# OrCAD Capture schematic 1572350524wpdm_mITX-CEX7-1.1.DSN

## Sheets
1 CEX7-Interface: size D; title: COM express type 7 interface; rev: 1.1
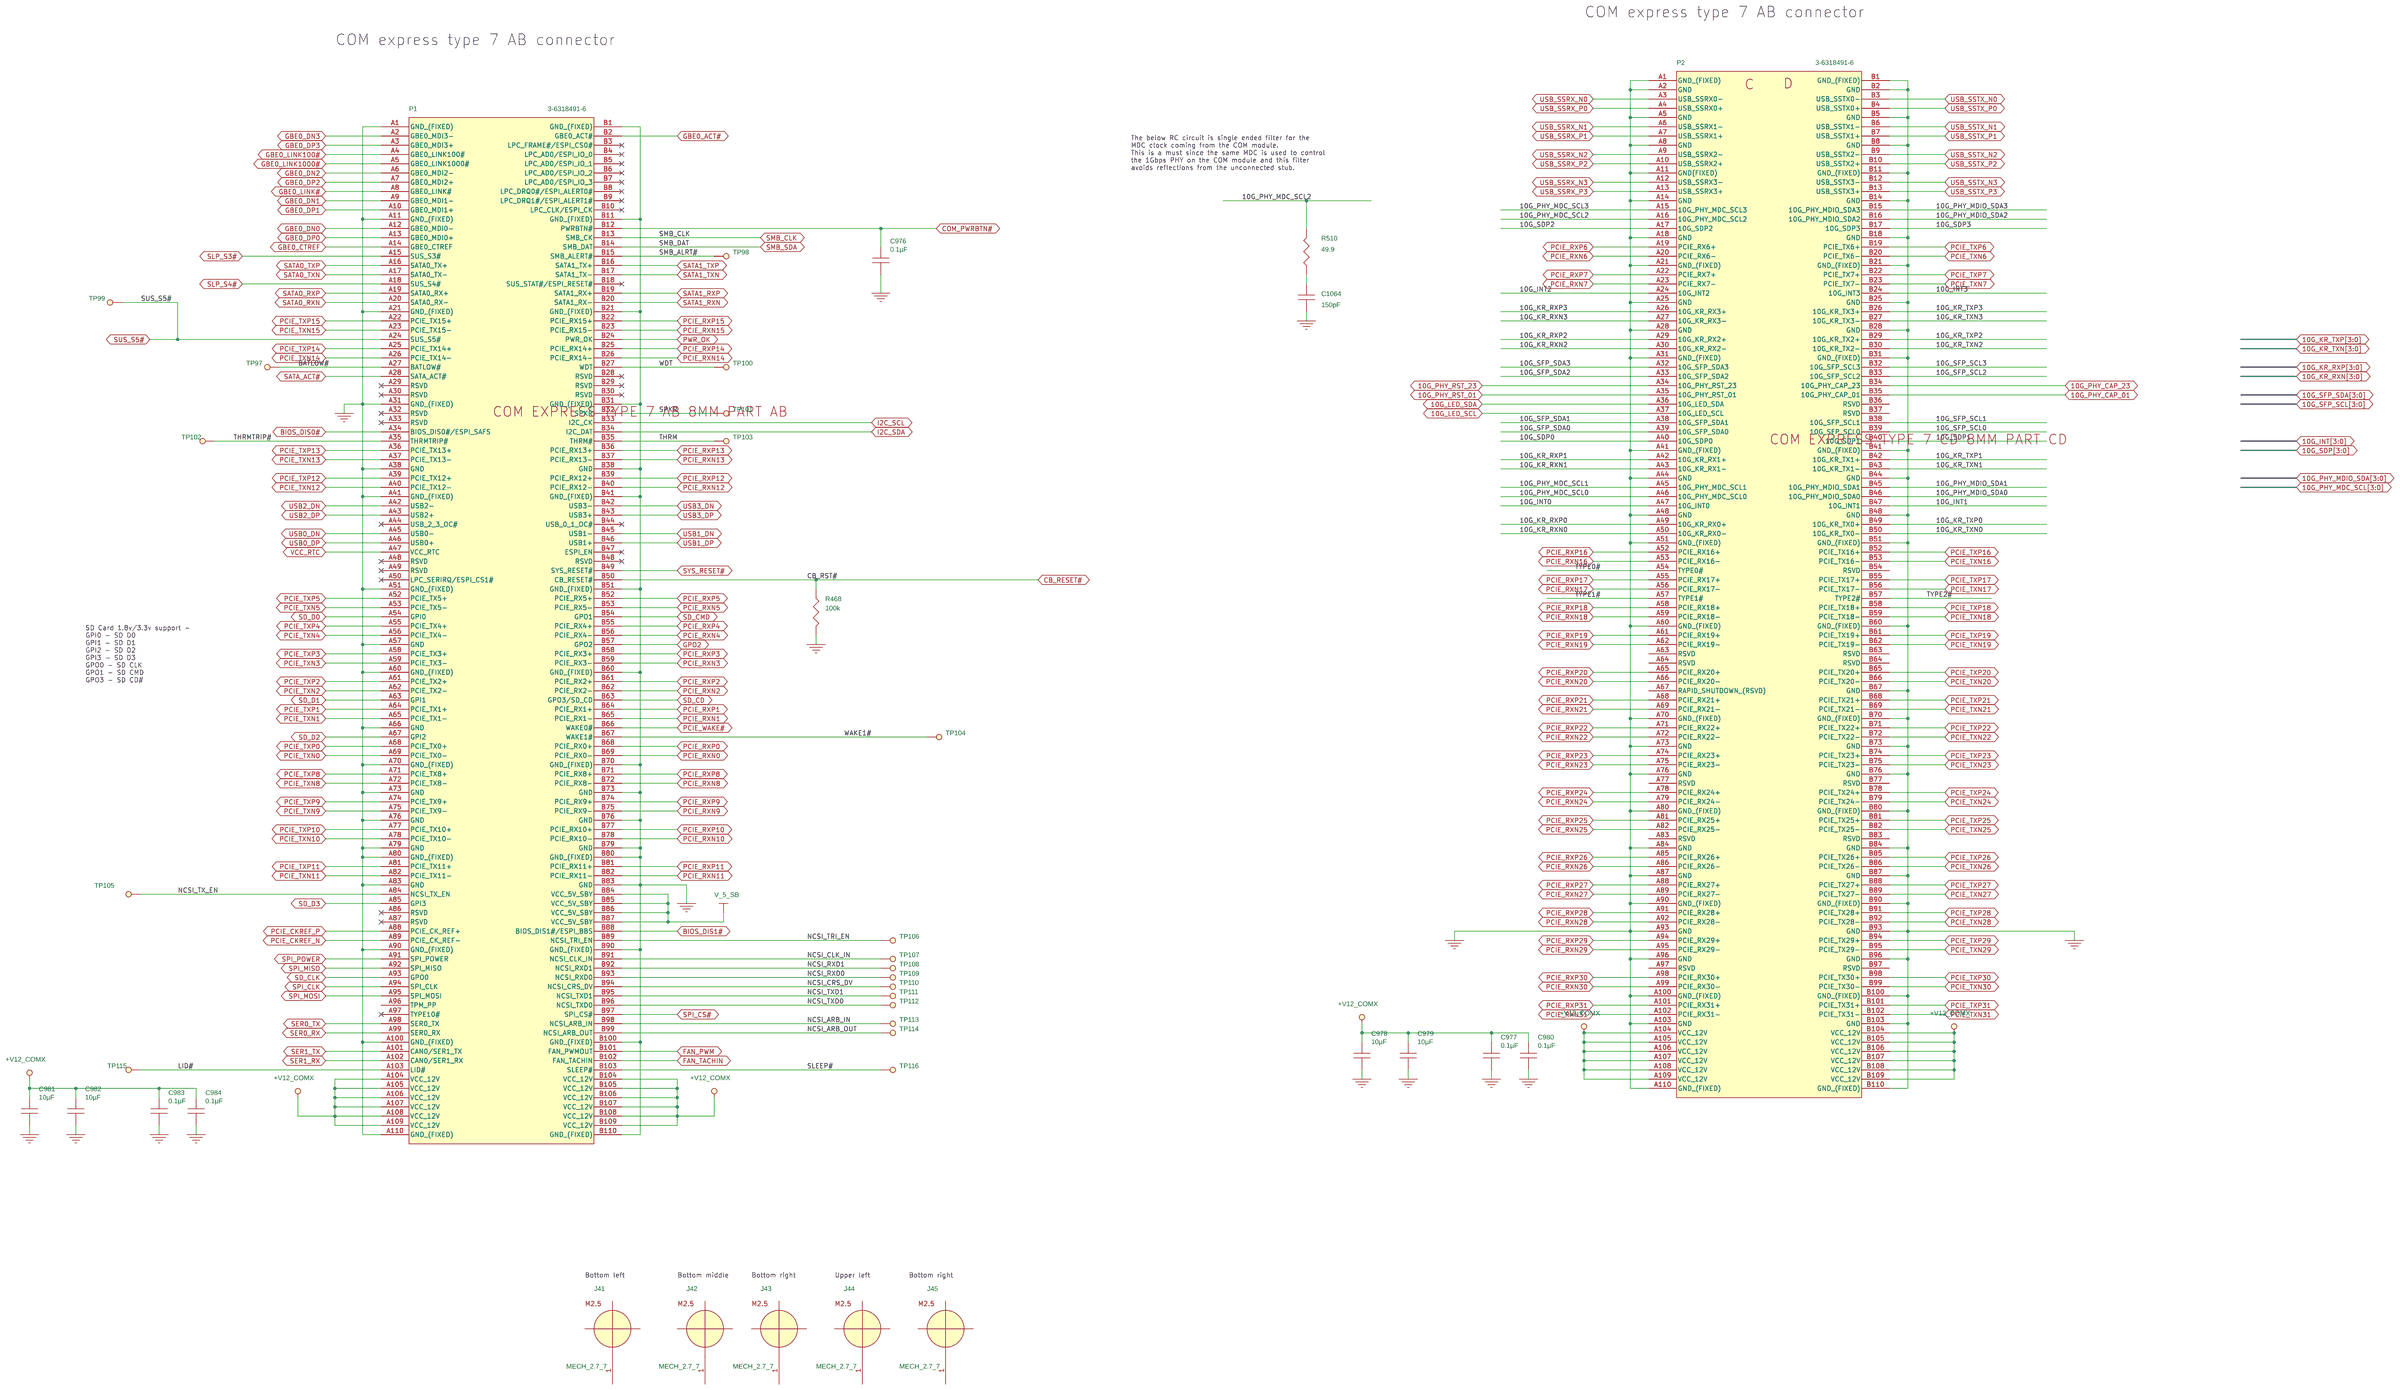
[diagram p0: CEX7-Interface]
2 Connectors: size D; title: PCIe, SATA, NVME, FANs, micro SD, RJ45 and QSFP28 connectors
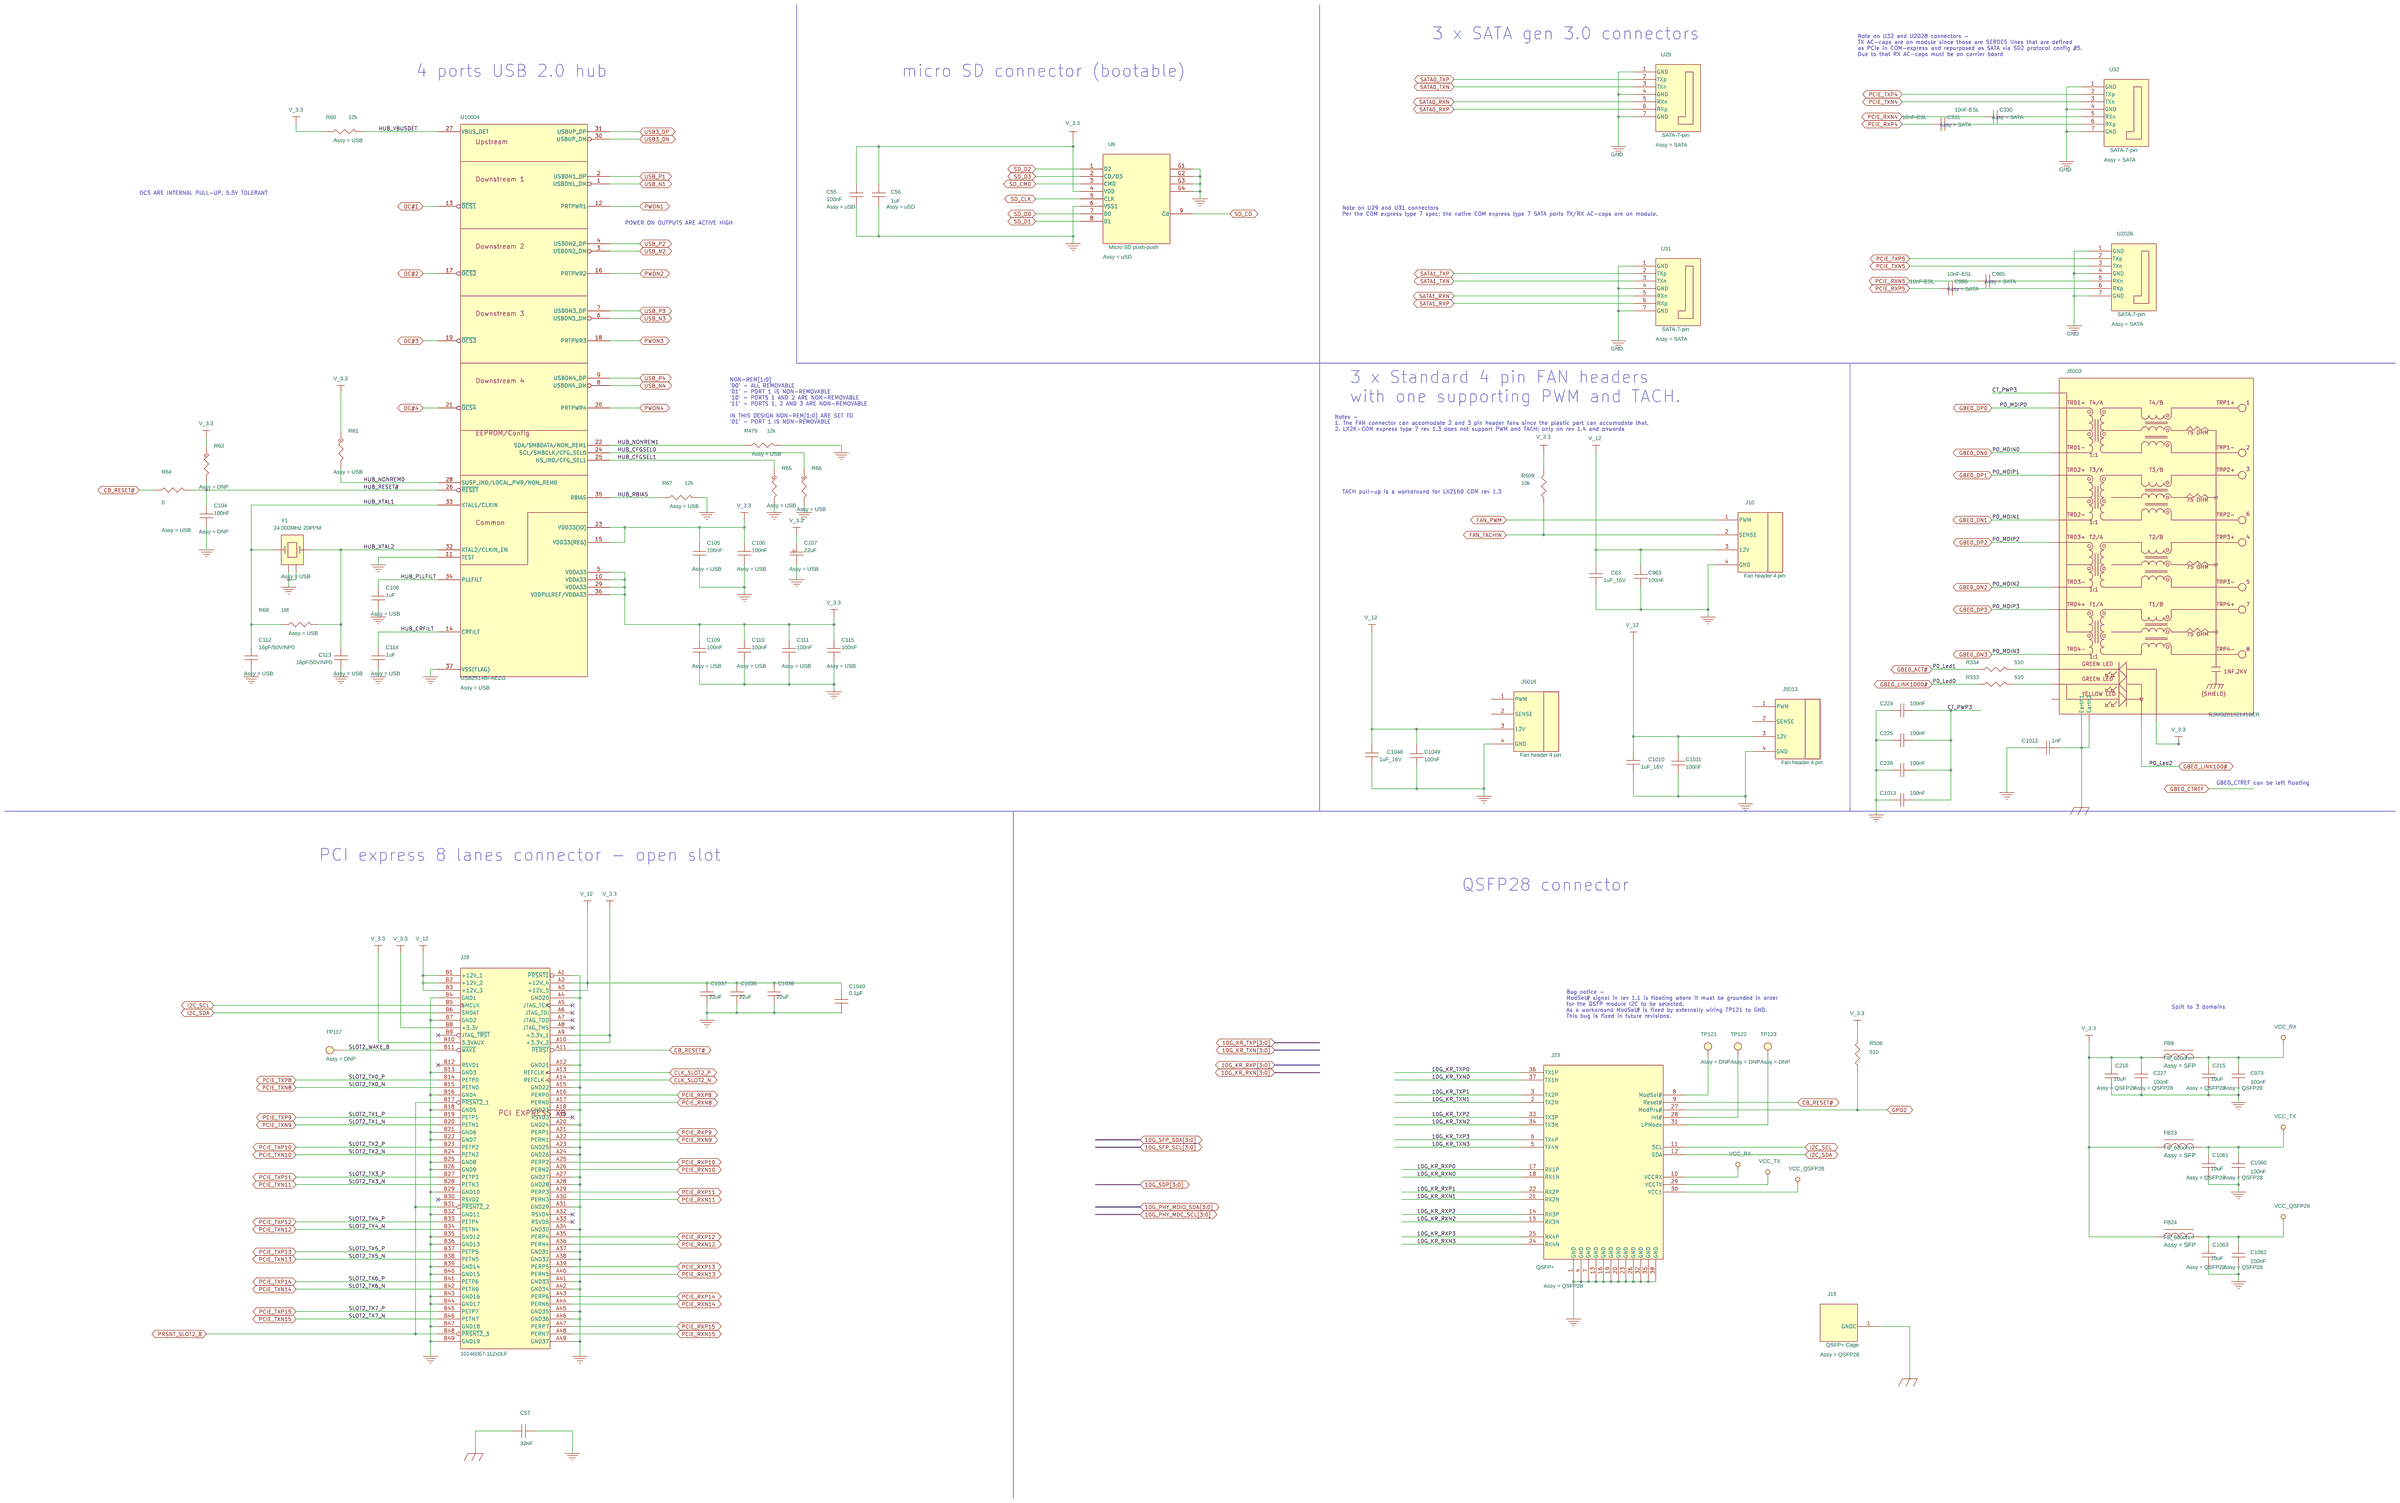
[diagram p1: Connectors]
3 Connectors (2): size D; title: Micro BMC, NVME, USB serial, USB connectors
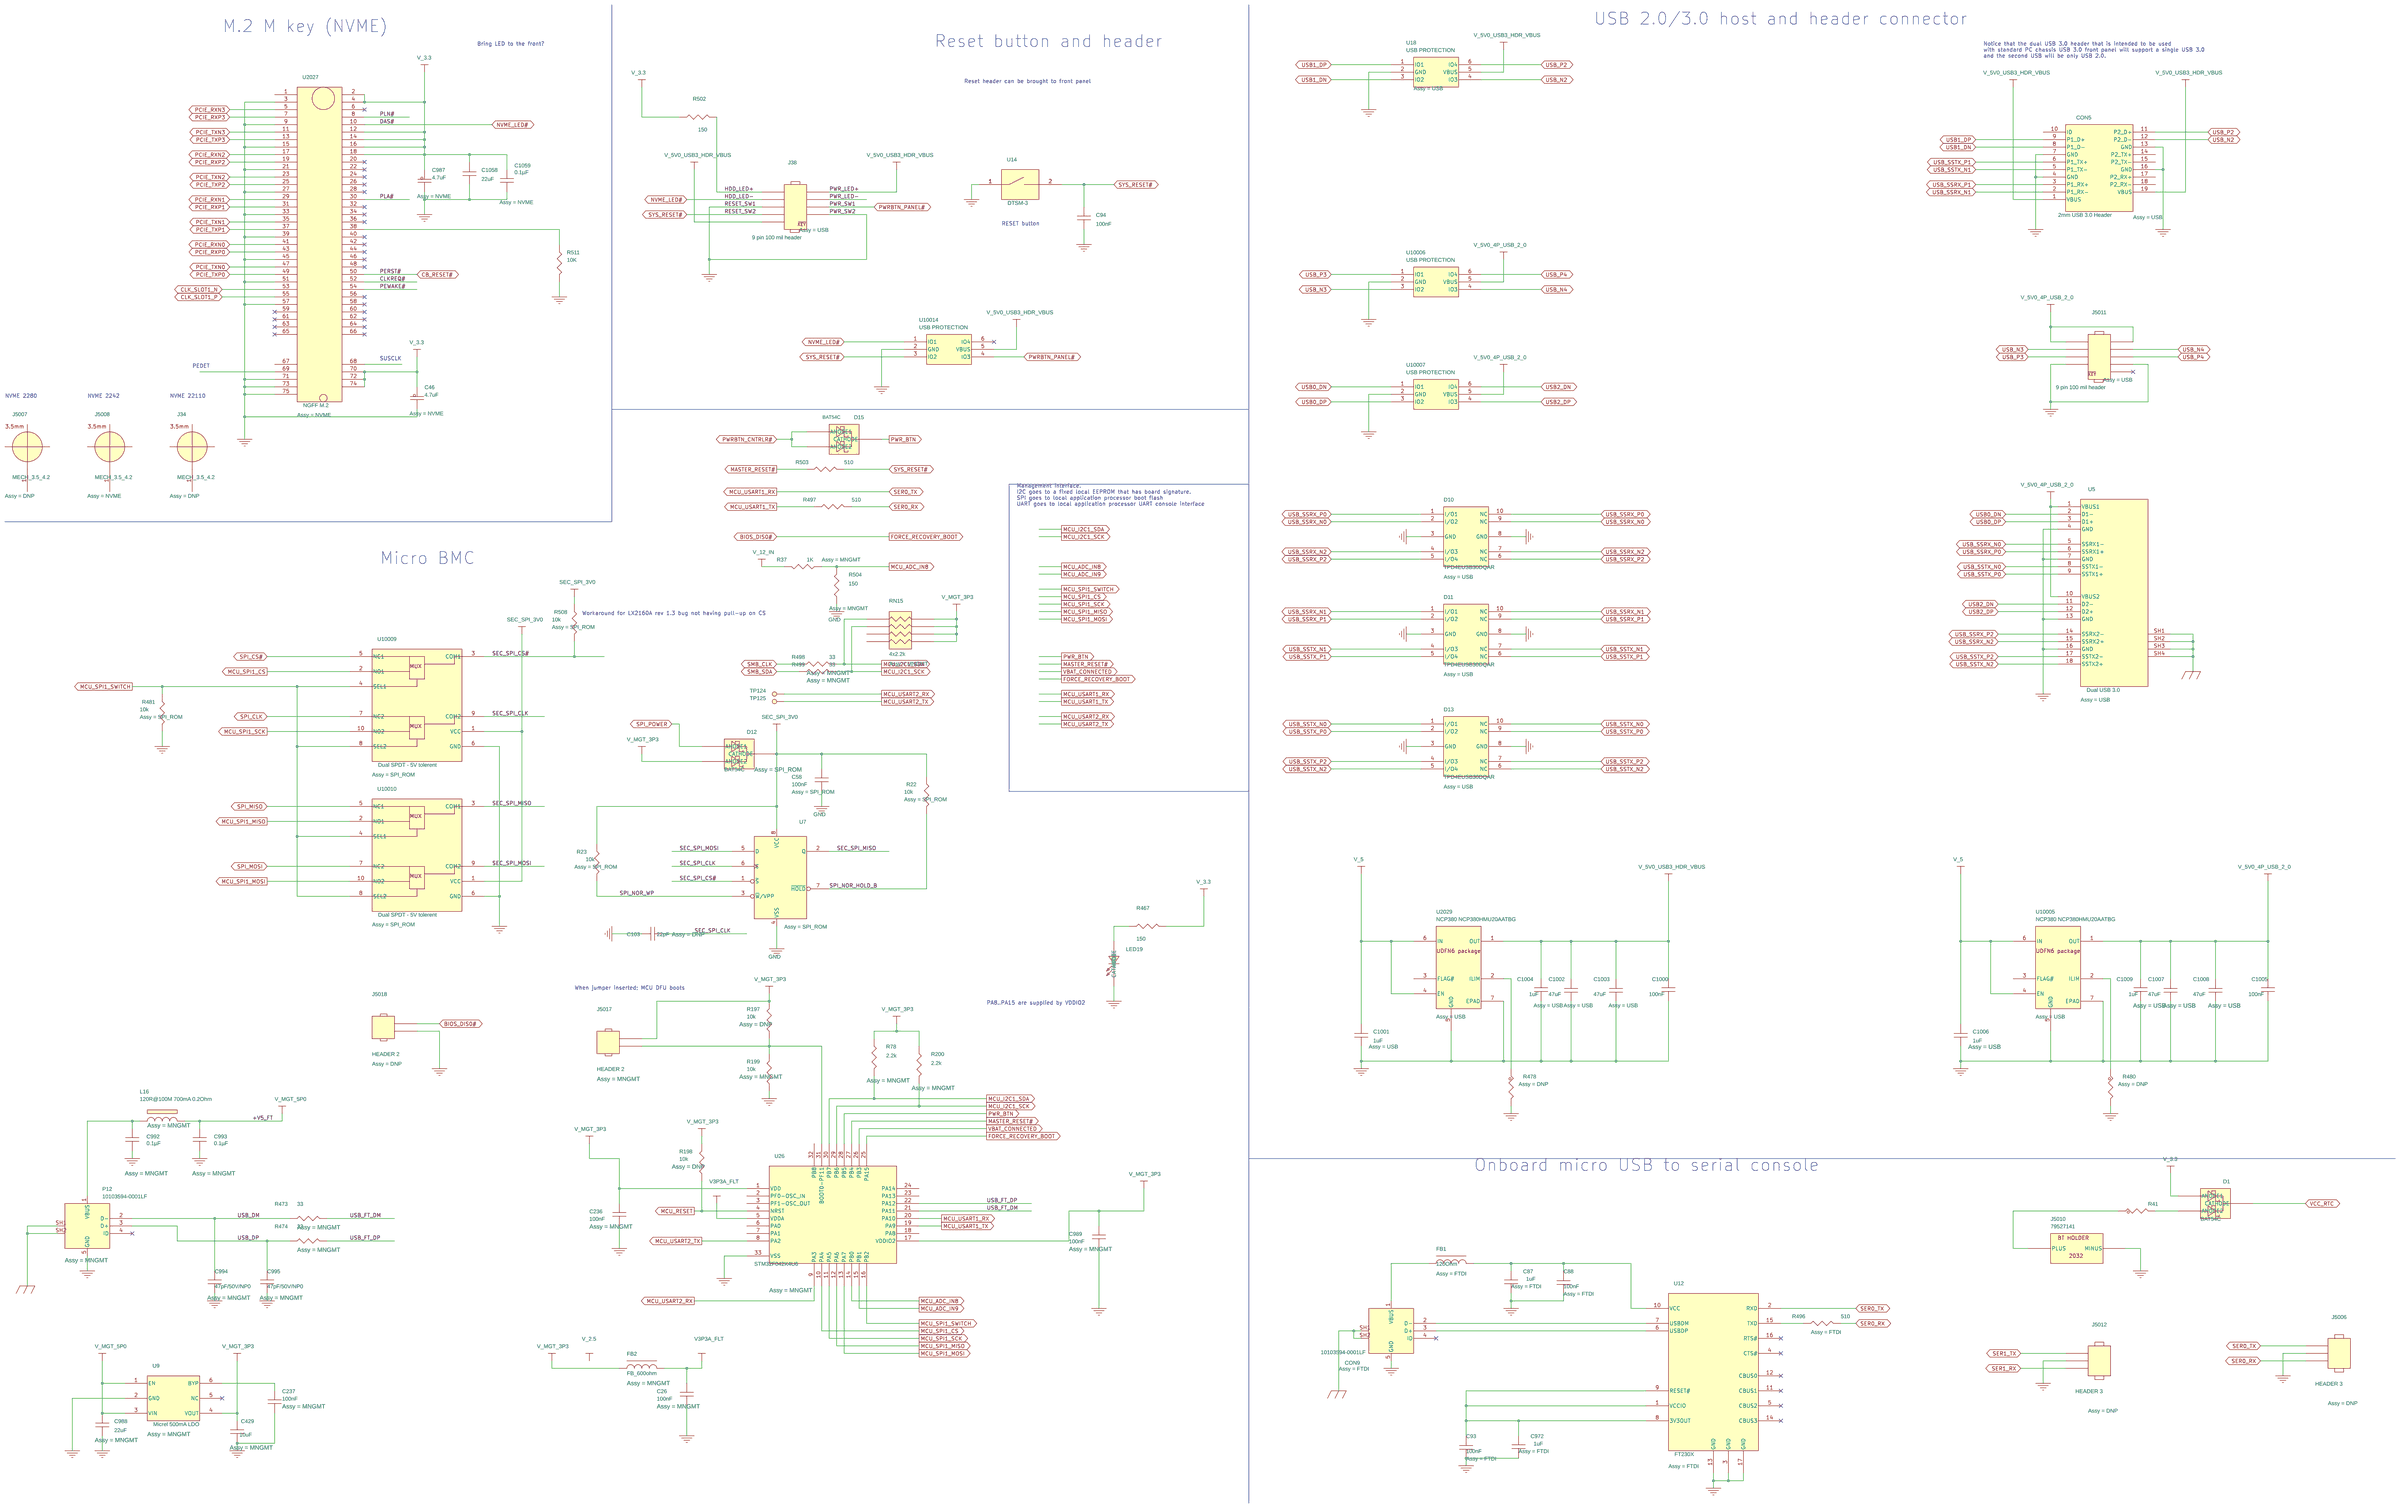
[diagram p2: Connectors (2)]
4 DC-DC: size D; title: ATX, 2x2 SFP+ connectors, power button controller; rev: 1.3
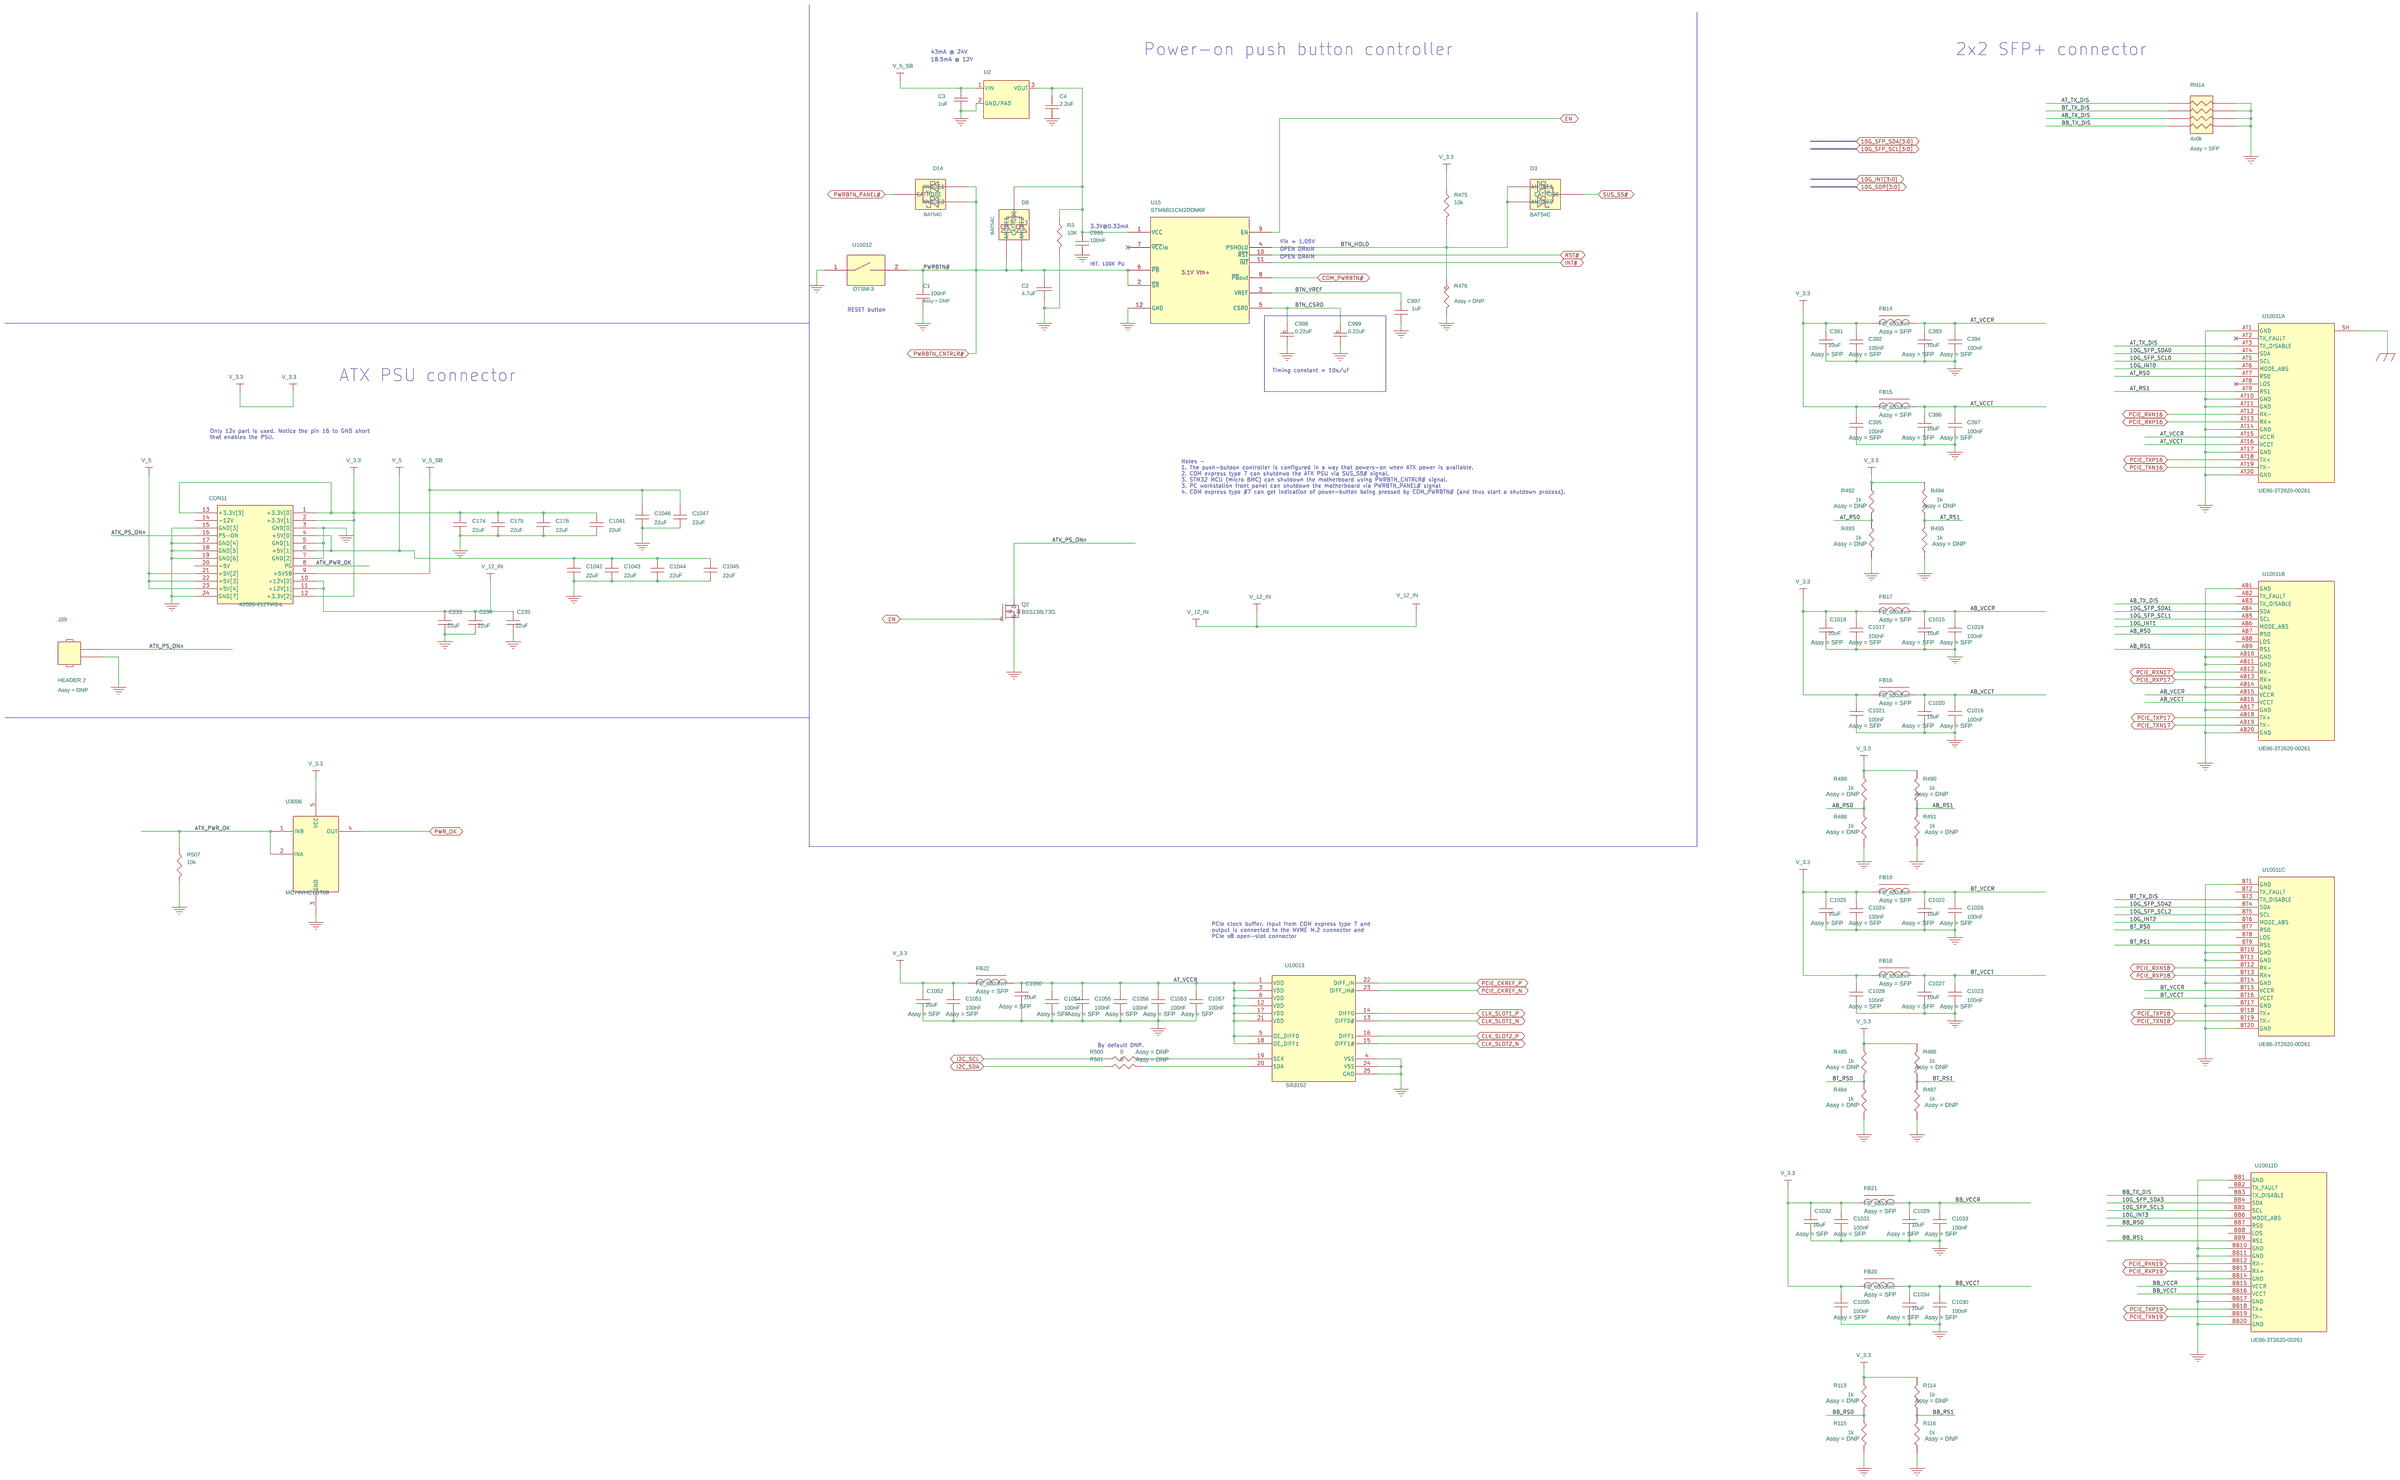
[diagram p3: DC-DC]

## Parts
sheet CEX7-Interface
C976  0.1µF  [RC0402]
C977  0.1µF  [RC0402]
C978  10µF  [RC0805]
C979  10µF  [RC0805]
C980  0.1µF  [RC0402]
C981  10µF  [RC0805]
C982  10µF  [RC0805]
C983  0.1µF  [RC0402]
C984  0.1µF  [RC0402]
C1064  150pF
J41  MECH_2.7_7  [MECH_2.5_4]
J42  MECH_2.7_7  [MECH_2.5_4]
J43  MECH_2.7_7  [MECH_2.5_4]
J44  MECH_2.7_7  [MECH_2.5_4]
J45  MECH_2.7_7  [MECH_2.5_4]
P1  3-6318491-6  [A107335-ND-AB]
P2  3-6318491-6  [A107335-ND-CD]
R468  100k  [RC0402]
R510  49.9
TP97  TESTPOINT  [TESTPOINT]
TP98  TESTPOINT  [TESTPOINT]
TP99  TESTPOINT  [TESTPOINT]
TP100  TESTPOINT  [TESTPOINT]
TP101  TESTPOINT  [TESTPOINT]
TP102  TESTPOINT  [TESTPOINT]
TP103  TESTPOINT  [TESTPOINT]
TP104  TESTPOINT  [TESTPOINT]
TP105  TESTPOINT  [TESTPOINT]
TP106  TESTPOINT  [TESTPOINT]
TP107  TESTPOINT  [TESTPOINT]
TP108  TESTPOINT  [TESTPOINT]
TP109  TESTPOINT  [TESTPOINT]
TP110  TESTPOINT  [TESTPOINT]
TP111  TESTPOINT  [TESTPOINT]
TP112  TESTPOINT  [TESTPOINT]
TP113  TESTPOINT  [TESTPOINT]
TP114  TESTPOINT  [TESTPOINT]
TP115  TESTPOINT  [TESTPOINT]
TP116  TESTPOINT  [TESTPOINT]
sheet Connectors (2)
C26  100nF
C46  4.7uF
C58  100nF
C87  1uF
C88  100nF
C93  100nF
C94  100nF
C103  22pF
C236  100nF
C237  100nF
C429  10uF
C972  1uF
C987  4.7uF
C988  22uF
C989  100nF
C992  0.1µF  [RC0402]
C993  0.1µF  [RC0402]
C994  47pF/50V/NP0  [311-1021-1-ND]
C995  47pF/50V/NP0  [311-1021-1-ND]
C1000  100nF
C1001  1uF
C1002  47uF
C1003  47uF
C1004  1uF
C1005  100nF
C1006  1uF
C1007  47uF
C1008  47uF
C1009  1uF
C1058  22uF
C1059  0.1µF  [RC0402]
CON5  2mm USB 3.0 Header
CON9  10103594-0001LF
D1  BAT54C
D10  TPD4EUSB30DQAR  [296-28063-1-ND]
D11  TPD4EUSB30DQAR  [296-28063-1-ND]
D12  BAT54C
D13  TPD4EUSB30DQAR  [296-28063-1-ND]
D15  BAT54C
FB1  120Ohm
FB2  FB_600ohm
J34  MECH_3.5_4.2  [MECH_2.5_4]
J38  9 pin 100 mil header
J5006  HEADER 3
J5007  MECH_3.5_4.2  [MECH_2.5_4]
J5008  MECH_3.5_4.2  [MECH_2.5_4]
J5010  79527141  [BT00006]
J5011  9 pin 100 mil header
J5012  HEADER 3
J5017  HEADER 2
J5018  HEADER 2
L16  120R@100M 700mA 0.2Ohm  [240-2367-1-ND]
LED19  SMT Green
P12  10103594-0001LF
R22  10k
R23  10k
R37  1K
R41  1K
R78  2.2k
R197  10k
R198  10k
R199  10k
R200  2.2k
R467  150
R473  33  [RC0402]
R474  33  [RC0402]
R478  0
R480  0
R481  10k
R496  510
R497  510
R498  33  [RC0402]
R499  33  [RC0402]
R502  150
R503  510
R504  150
R508  10k
R511  10K  [0402]
RN15  4x2.2k
TP124  TESTPOINT  [TESTPOINT]
TP125  TESTPOINT  [TESTPOINT]
U5  Dual USB 3.0
U7  W25Q32BVZPIG
U9  Micrel 500mA LDO
U12  FT230X  [QFN16]
U14  DTSM-3  [DTSM-3]
U18  USB PROTECTION  [568-3529-1-ND]
U26  STM32F042K4U6  [UFQFPN32_5x5]
U2027  NGFF M.2  [NGFF]
U2029  NCP380 NCP380HMU20AATBG  [TSOP-5]
U10005  NCP380 NCP380HMU20AATBG  [TSOP-5]
U10006  USB PROTECTION  [568-3529-1-ND]
U10007  USB PROTECTION  [568-3529-1-ND]
U10009  Dual SPDT - 5V tolerent  [R-PUQFN-N10]
U10010  Dual SPDT - 5V tolerent  [R-PUQFN-N10]
U10014  USB PROTECTION  [568-3529-1-ND]
sheet Connectors
C55  100nF
C56  1uF
C57  33nF
C63  1uF_16V
C104  100nF
C105  100nF
C106  100nF
C107  22uF
C108  1uF
C109  100nF
C110  100nF
C111  100nF
C112  16pF/50V/NP0  [1276-1646-1-ND]
C113  16pF/50V/NP0  [1276-1646-1-ND]
C114  1uF
C115  100nF
C215  10uF
C216  10uF
C224  100nF
C225  100nF
C226  100nF
C227  100nF
C330  10nF-ESL
C331  10nF-ESL
C963  100nF
C973  100nF
C985  10nF-ESL
C986  10nF-ESL
C1010  1uF_16V
C1011  100nF
C1012  1nF
C1013  100nF
C1036  22uF
C1037  22uF
C1038  22uF
C1040  0.1µF  [RC0402]
C1048  1uF_16V
C1049  100nF
C1060  100nF
C1061  10uF
C1062  100nF
C1063  10uF
FB9  FB_600ohm
FB23  FB_600ohm
FB24  FB_600ohm
J10  Fan header 4 pin  [22-23-2041]
J15  QSFP+ Cage
J23  QSFP+
J28  10146067-112x0LF
J5003  RJMG20162141BER
J5013  Fan header 4 pin  [22-23-2041]
J5016  Fan header 4 pin  [22-23-2041]
R60  12k  [RC0402]
R61  100K
R63  100K
R64  0  [RC0402]
R65  100K
R66  100K
R67  12k  [RC0402]
R68  1M  [RC0402]
R333  510
R334  510
R479  12k  [RC0402]
R506  510
R509  10k
TP117  TP
TP121  TP
TP122  TP
TP123  TP
U6  Micro SD push-push  [CJ-WK21923-R6SS6]
U29  SATA-7-pin  [SATA-7-PIN]
U31  SATA-7-pin  [SATA-7-PIN]
U32  SATA-7-pin  [SATA-7-PIN]
U2028  SATA-7-pin  [SATA-7-PIN]
U10004  USB2514BI-AEZG  [USB2514BI-AEZG-ND]
Y1  24.000MHz 20PPM  [SER3634CT-ND]
sheet DC-DC
C1  100nF
C2  4.7uF  [C0805]
C3  1uF
C4  2.2uF
C174  22uF
C175  22uF
C176  22uF
C233  22uF
C234  22uF
C235  22uF
C391  10uF
C392  100nF
C393  10uF
C394  100nF
C395  100nF
C396  10uF
C397  100nF
C996  100nF
C997  1uF
C998  0.22uF
C999  0.22uF
C1015  10uF
C1016  100nF
C1017  100nF
C1018  10uF
C1019  100nF
C1020  10uF
C1021  100nF
C1022  10uF
C1023  100nF
C1024  100nF
C1025  10uF
C1026  100nF
C1027  10uF
C1028  100nF
C1029  10uF
C1030  100nF
C1031  100nF
C1032  10uF
C1033  100nF
C1034  10uF
C1035  100nF
C1041  22uF
C1042  22uF
C1043  22uF
C1044  22uF
C1045  22uF
C1046  22uF
C1047  22uF
C1050  10uF
C1051  100nF
C1052  10uF
C1053  100nF
C1054  100nF
C1055  100nF
C1056  100nF
C1057  100nF
CON11  4200S-212TW2-L
D3  BAT54C
D8  BAT54C
D14  BAT54C
FB14  FB_600ohm
FB15  FB_600ohm
FB16  FB_600ohm
FB17  FB_600ohm
FB18  FB_600ohm
FB19  FB_600ohm
FB20  FB_600ohm
FB21  FB_600ohm
FB22  FB_600ohm
J39  HEADER 2
Q2  BSS138LT3G  [BSS138LT3GOSTR-ND]
R3  10K  [0402]
R113  1k
R114  1k
R115  1k
R116  1k
R475  10k
R476  30K
R484  1k
R485  1k
R486  1k
R487  1k
R488  1k
R489  1k
R490  1k
R491  1k
R492  1k
R493  1k
R494  1k
R495  1k
R500  0
R501  0
R507  10k
RN14  4x0k
U2  LDO 3.3V
U15  STM6601CM2DDM6F  [497-10132-1-ND]
U3006  MC74VHC1GT08  [SOT-353]
U10011  UE86-3T2620-00261  (sections A,B,C,D)
U10012  DTSM-3  [DTSM-3]
U10013  Si53152

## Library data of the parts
C976 C977 C980 C983 C984 C1040 = CAP_CER_0.1UF_16V_10%_X7R_0402: SolidRun P/N: CA20013
C978 C979 C981 C982 = CAP_CER_10UF_25V_10%_X5R_0805: SolidRun P/N: CA40005
C1064 = Cap: CAP CER 0402 150pF 50V 5% COG; SolidRun P/N: CA20827
J41-J45 = MECH_0.5_4: SolidRun P/N: MCH00072
P1 = COM-EXPRESS_BASE_TYP_7_CONN_AB: SolidRun P/N: CO00676
P2 = COM-EXPRESS_BASE_TYP_7_CONN_CD: SolidRun P/N: CO00676
R468 = RES_100K_OHM_1_16W_1%_0402_SMD: SolidRun P/N: RE20482
R510 = Resistor: RES 0402 1/16W 49.9 1%; SolidRun P/N: RE20011
TP97-TP116 TP124 TP125 = TESTPOINT: Assy: DNP; SolidRun P/N: TP00001
C26 C236 C237 C989 = Cap: CAP CER 0402 100nF 10V 10% X7R; Assy: MNGMT; SolidRun P/N: CA20001
C46 C987 = CAP_NP: CAP CER 4.7 6.3V 10% X5R 0402; Assy: NVME; SolidRun P/N: CA20800
C58 = Cap: Assy: SPI_ROM; SolidRun P/N: CA20001
C87 C972 = Cap: Assy: FTDI; SolidRun P/N: CA20005
C88 C93 = Cap: Assy: FTDI; SolidRun P/N: CA20001
C94 C963 C1000 C1005 C1011 C1049 = Cap: SolidRun P/N: CA20001
C103 = Cap: CAP CER 0402 22pF 50V 5% C0G; Assy: DNP; SolidRun P/N: CA20080
C429 = Cap: Assy: MNGMT; SolidRun P/N: CA30001
C988 = Cap: CAP CER 0603 22UF 6.3V 20% X5R; Assy: MNGMT; SolidRun P/N: CA30002
C992 C993 = CAP_CER_0.1UF_16V_10%_X7R_0402: Assy: MNGMT; SolidRun P/N: CA20013
C994 C995 = CAP_CER_47PF_50V_5%_NPO_0402: Assy: MNGMT; SolidRun P/N: CA20144
C1001 C1004 C1006 C1009 = Cap: Assy: USB; SolidRun P/N: CA20005
C1002 C1003 C1007 C1008 = Cap: Assy: USB; SolidRun P/N: CA50001
C174-C176 C1041-C1047 C1058 = Cap: CAP CER 0603 22UF 6.3V 20% X5R; SolidRun P/N: CA30002
C1059 = CAP_CER_0.1UF_16V_10%_X7R_0402: Assy: NVME; SolidRun P/N: CA20013
CON5 = BH1S-20G_JTAG_3: Assy: USB; SolidRun P/N: CO00758
CON9 = CU04SCH15B0_1: Assy: FTDI; SolidRun P/N: CO00005
D1 D3 D8 D14 D15 = BAT54C: SolidRun P/N: DI00001
D10 D11 D13 = TVS_ESD_USB3.0_4CH_10SON: Assy: USB; SolidRun P/N: DI00247
D12 = BAT54C: Assy: SPI_ROM; SolidRun P/N: DI00001
FB1 = Ferrite_Bead: Assy: FTDI; SolidRun P/N: IN00003
FB2 = Ferrite_Bead: Multilayer Ferrite Chip Beads 0402 600ohm 500mA +/-25%; Assy: MNGMT; SolidRun P/N: IN00013
J34 J5007 = MECH_4.5_4: Assy: DNP; SolidRun P/N: MCH0008
J38 = HEADER_4x2_SM_5: Assy: USB; SolidRun P/N: CO00733
J5006 J5012 = HEADER_3: Assy: DNP; SolidRun P/N: CO00509
J5008 = MECH_4.5_4: Assy: NVME; SolidRun P/N: MCH0008
J5010 = CONN_BATT_HOLDER_2032_79527141
J5011 = HEADER_4x2_SM_4: Assy: USB; SolidRun P/N: CO00759
J5017 = HEADER_2: Assy: MNGMT; SolidRun P/N: CO00049
J39 J5018 = HEADER_2: Assy: DNP; SolidRun P/N: CO00049
L16 = FERRITE_700MA_120_OHM_0603_SMD: Assy: MNGMT; SolidRun P/N: IN00104
LED19 = LED: SolidRun P/N: DI00008
P12 = CU04SCH15B0_1: microUSB Type B connector; Assy: MNGMT; SolidRun P/N: CO00005
R22 R23 R481 R508 = Resistor: Assy: SPI_ROM; SolidRun P/N: RE20013
R37 = Resistor: RES 0402 1/16W 1K 5%; Assy: MNGMT; SolidRun P/N: RE20010
R41 = RES: SolidRun P/N: RE20010
R78 R200 = Resistor: CHIP RES 2.2K 1/16W 0402; Assy: MNGMT; SolidRun P/N: RE20204
R197 R198 = Resistor: RES 0402 1/16W 10K? 1%; Assy: DNP; SolidRun P/N: RE20013
R199 = Resistor: RES 0402 1/16W 10K? 1%; Assy: MNGMT; SolidRun P/N: RE20013
R467 R502 = Resistor: SolidRun P/N: RE20014
R473 R474 R498 R499 = RES_33.0_OHM_1_16W_1%_0402_SMD: Assy: MNGMT; SolidRun P/N: RE20502
R478 R480 = RES: Assy: DNP; SolidRun P/N: RE20009
R496 = RES1: RES SMD 510 OHM 5% 1/16W 0402; Assy: FTDI; SolidRun P/N: RE20022
R497 R503 = RES1: RES SMD 510 OHM 5% 1/16W 0402; Assy: MNGMT; SolidRun P/N: RE20022
R504 = Resistor: Assy: MNGMT; SolidRun P/N: RE20014
R3 R511 = R-10K-0402
RN15 = RESISTOR_DIP_4: 4 Elements 2.2kOhms 5 %; Assy: MNGMT; SolidRun P/N: RN00045
U5 = Dual_USB_3_0.0: Assy: USB; SolidRun P/N: CO00554
U7 = M25P32: Assy: SPI_ROM; SolidRun P/N: IC00311
U9 = Micrel_500mA_LDO: Low Dropout LDO, 3.3V/500mA; Assy: MNGMT; SolidRun P/N: IC00123
U12 = FT230X_4: Assy: FTDI; SolidRun P/N: IC00015
U14 U10012 = DTSM-3: SolidRun P/N: CO00098
U18 U10006 U10007 = IC_USB_DUAL_ESD_PROTECT_6TSOP: Assy: USB; SolidRun P/N: IC01197
U26 = STM32F042K4U6_1: Assy: MNGMT; SolidRun P/N: IC01015
U2027 = NGFF_M.2: Assy: NVME; SolidRun P/N: CO00514
U2029 U10005 = NCP380_2: Assy: USB; SolidRun P/N: IC01034
U10009 U10010 = Dual_SPDT: Dual analog switch; Assy: SPI_ROM; SolidRun P/N: IC01039
U10014 = IC_USB_DUAL_ESD_PROTECT_6TSOP: SolidRun P/N: IC01197
C55 = Cap: Assy: uSD; SolidRun P/N: CA20001
C56 = Cap: Assy: uSD; SolidRun P/N: CA20005
C57 = Cap: SolidRun P/N: CA20011
C63 C1010 C1048 = Cap: SolidRun P/N: CA30013
C104 = Cap: CAP CER 0402 100nF 10V 10% X7R; Assy: DNP; SolidRun P/N: CA20001
C105 C106 C109-C111 C115 = Cap: CAP CER 0402 100nF 10V 10% X7R; Assy: USB; SolidRun P/N: CA20001
C107 = CAP_NP: CAP CER 22UF 6.3V 20% X5R 0603; Assy: USB; SolidRun P/N: CA30002
C108 C114 = Cap: CAP CER 1uF 10V 10% X5R 0402; Assy: USB; SolidRun P/N: CA20005
C112 C113 = CAP_CER_16PF_50V_5%_NP0_0402: Assy: USB; SolidRun P/N: CA20134
C215 C216 C1061 C1063 = Cap: CAP CER 10UF 6.3V 10% X5R 0603; Assy: QSFP28; SolidRun P/N: CA30001
C224-C226 C1013 = CAP_NP1: CAP CER 0.1uF ±10% 50V X7R 0402; SolidRun P/N: CA20147
C227 C973 C1060 C1062 = Cap: CHIP CAP 0.1uF 6.3V 0402 X5R; Assy: QSFP28; SolidRun P/N: CA20001
C330 C331 C985 C986 = Cap: Assy: SATA; SolidRun P/N: CA20002
C1012 = CAP_NP1: CAP CER 1nF ±10% 1KV X7R 1206; SolidRun P/N: CA50002
C233-C235 C1036-C1038 = Cap: SolidRun P/N: CA60006
FB9 FB14-FB24 = Ferrite_Bead: Multilayer Ferrite Chip Beads 0603 600ohm 1.3A +/-25%; Assy: SFP; SolidRun P/N: IN00068
J10 J5013 J5016 = Fan_header_4_pin: SolidRun P/N: CO00640
J15 = QSFP+_Cage: Assy: QSFP28; SolidRun P/N: CO00707
J23 = QSFP+: Assy: QSFP28; SolidRun P/N: CO00706
J28 = CONN_PCI_EXPRESS_X8: CON 2X49 PCI EXPRESS SMT 1MM SP 320H AU; SolidRun P/N: CO00731
J5003 = J-RJMG20162141BER-FCI: CONN MAGJACK 1PORT 1000 BASE-T; SolidRun P/N: CO00673
R60 R67 R479 = RES_12.0K_OHM_1_16W_1%_0402_SMD: Assy: USB; SolidRun P/N: RE20462
R61 R65 R66 = RES: RES MF 100K 1/16W 0402; Assy: USB; SolidRun P/N: RE20015
R63 = RES: RES MF 100K 1/16W 0402; Assy: DNP; SolidRun P/N: RE20015
R64 = RES_0.0_OHM_1_16W_0402_SMD: Assy: USB; SolidRun P/N: RE20009
R68 = RES_1.00M_OHM_1_16W_1%_0402_SMD: Assy: USB; SolidRun P/N: RE20416
R333 R334 R506 = RES1: RES SMD 510 OHM 5% 1/16W 0402; SolidRun P/N: RE20022
R475 R507 R509 = Resistor: RES 0402 1/16W 10K? 1%; SolidRun P/N: RE20013
TP117 TP121-TP123 = TestPoint: Assy: DNP; SolidRun P/N: TP00001
U6 = CJ-WK21923-R6SS6_0: Assy: uSD; SolidRun P/N: CO00091
U29 U31 U32 U2028 = SATA-7-pin: Assy: SATA; SolidRun P/N: CO00581
U10004 = IC_USB_2.0_HUB_4P_IND_36QFNE3: Assy: USB; SolidRun P/N: IC01084
Y1 = CRYSTAL_24MHZ_9PF_40Ohm_20ppm: Assy: USB; SolidRun P/N: OC00003
C1 = Cap: CHIP CAP 0.1uF 6.3V 0402 X5R; Assy: DNP; SolidRun P/N: CA20001
C2 = CAP-47uF-6.3V-0805: CAP CER 4.7UF 6.3V 10% X5R 0603; SolidRun P/N: CA30003
C3 = CAP-1uF-35V-0402
C4 = CAP-2.2uF-6.3V-0402
C391 C393 C396 C1015 C1018 C1020 C1022 C1025 C1027 C1029 C1032 C1034 C1050 C1052 = Cap: CAP CER 0603 10UF 6.3V 10% X5R; Assy: SFP; SolidRun P/N: CA30001
C392 C394 C395 C397 C1016 C1017 C1019 C1021 C1023 C1024 C1026 C1028 C1030 C1031 C1033 C1035 C1051 C1053-C1057 = Cap: CAP CER 0402 100nF 10V 10% X7R; Assy: SFP; SolidRun P/N: CA20001
C996 = Cap: CHIP CAP 0.1uF 6.3V 0402 X5R; SolidRun P/N: CA20001
C997 = Cap: CAP CER 0402 1uF 25V 20% X5R; SolidRun P/N: CA20132
C998 C999 = CAP_NP: 0.22uF ±10% 100V Ceramic Capacitor X7R 0805; SolidRun P/N: CA40009
CON11 = 5566_ATX: SolidRun P/N: CO00590
Q2 = MOSFET_N-CH_50V_200MA_SOT-23: SolidRun P/N: TR00007
R113-R116 R484-R495 = Resistor: RES 0402 1/16W 1k 5%; Assy: DNP; SolidRun P/N: RE20010
R476 = RES: Assy: DNP; SolidRun P/N: RE20458
R500 R501 = Resistor: RES 0402 1/16W 0? 5%; Assy: DNP; SolidRun P/N: RE20009
RN14 = RESISTOR_DIP_4: 4 Elements zero ohms; Assy: SFP; SolidRun P/N: RN00039
U2 = U-LDO-3.3V-AP2204R
U15 = IC_PWR_BTN_CTL_ACTHI_3.1V_5.6S: IC SUPERVISOR 3.1V 12TDFN BUTON CONTROLLER ON/OFF CTRL; SolidRun P/N: IC01227
U3006 = MC74VHC1GT08: SolidRun P/N: IC00024
U10011 = UE86-3T2620-00261: Assy: SFP; SolidRun P/N: CO00735
U10013 = Si53152: 1:2 PCIe clock buffer gen 4; SolidRun P/N: IC01396

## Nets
+V12_COMX: C63.1 C233.1 C234.1 C235.1 C963.2 C977.1 C978.1 C979.1 C980.1 C981.1 C982.1 C983.1 C984.1 C1010.1 C1011.2 C1036.1 C1037.1 C1038.1 C1040.1 C1048.1 C1049.2 CON11.10(+12V[0]) CON11.11(+12V[1]) J10.3(12V) J28.A2(+12V_4) J28.A3(+12V_5) J28.B1(+12V_1) J28.B2(+12V_2) J28.B3(+12V_3) J5013.3(12V) J5016.3(12V) P1.A104(VCC_12V) P1.A105(VCC_12V) P1.A106(VCC_12V) P1.A107(VCC_12V) P1.A108(VCC_12V) P1.A109(VCC_12V) P1.B104(VCC_12V) P1.B105(VCC_12V) P1.B106(VCC_12V) P1.B107(VCC_12V) P1.B108(VCC_12V) P1.B109(VCC_12V) P2.A104(VCC_12V) P2.A105(VCC_12V) P2.A106(VCC_12V) P2.A107(VCC_12V) P2.A108(VCC_12V) P2.A109(VCC_12V) P2.B104(VCC_12V) P2.B105(VCC_12V) P2.B106(VCC_12V) P2.B107(VCC_12V) P2.B108(VCC_12V) P2.B109(VCC_12V) R37.2
GND: C1.2 C2.2 C3.2 C4.2 C26.2 C46.2 C55.2 C56.2 C57.2 C58.2 C63.2 C87.2 C88.1 C93.1 C94.2 C103.1 C104.2 C105.2 C106.2 C107.2 C108.2 C109.2 C110.2 C111.2 C112.2 C113.2 C114.2 C115.2 C174.1 C175.1 C176.1 C215.2 C216.2 C224.1 C225.1 C226.1 C227.2 C233.2 C234.2 C235.2 C236.2 C237.2 C391.2 C392.2 C393.2 C394.2 C395.2 C396.2 C397.2 C429.2 C963.1 C972.2 C973.2 C976.2 C977.2 C978.2 C979.2 C980.2 C981.2 C982.2 C983.2 C984.2 C987.2 C988.1 C989.2 C992.2 C993.2 C994.2 C995.2 C996.2 C997.1 C998.2 C999.2 C1000.2 C1001.1 C1002.1 C1003.1 C1004.2 C1005.2 C1006.1 C1007.1 C1008.1 C1009.2 C1010.2 C1011.1 C1012.2 C1013.1 C1015.2 C1016.2 C1017.2 C1018.2 C1019.2 C1020.2 C1021.2 C1022.2 C1023.2 C1024.2 C1025.2 C1026.2 C1027.2 C1028.2 C1029.2 C1030.2 C1031.2 C1032.2 C1033.2 C1034.2 C1035.2 C1036.2 C1037.2 C1038.2 C1040.2 C1041.1 C1042.1 C1043.1 C1044.1 C1045.1 C1046.1 C1047.1 C1048.2 C1049.1 C1050.2 C1051.2 C1052.2 C1053.2 C1054.2 C1055.2 C1056.2 C1057.2 C1058.1 C1059.2 C1060.2 C1061.2 C1062.2 C1063.2 C1064.2 CON5.4(GND) CON5.7(GND) CON5.13(GND) CON5.16(GND) CON9.5(GND) CON11.3(GND[0]) CON11.5(GND[1]) CON11.7(GND[2]) CON11.15(GND[3]) CON11.17(GND[4]) CON11.18(GND[5]) CON11.19(GND[6]) CON11.24(GND[7]) D10.3(GND) D10.8(GND) D11.3(GND) D11.8(GND) D13.3(GND) D13.8(GND) J10.4(GND) J23.1(GND) J23.4(GND) J23.7(GND) J23.13(GND) J23.16(GND) J23.19(GND) J23.20(GND) J23.23(GND) J23.26(GND) J23.32(GND) J23.35(GND) J23.38(GND) J28.A1(~{PRSNT1}) J28.A4(GND20) J28.A12(GND21) J28.A15(GND22) J28.A18(GND23) J28.A20(GND24) J28.A23(GND25) J28.A24(GND26) J28.A27(GND27) J28.A28(GND28) J28.A31(GND29) J28.A34(GND30) J28.A37(GND31) J28.A38(GND32) J28.A41(GND33) J28.A42(GND34) J28.A45(GND35) J28.A46(GND36) J28.A49(GND37) J28.B4(GND1) J28.B7(GND2) J28.B13(GND3) J28.B16(GND4) J28.B18(GND5) J28.B21(GND6) J28.B22(GND7) J28.B25(GND8) J28.B26(GND9) J28.B29(GND10) J28.B32(GND11) J28.B35(GND12) J28.B36(GND13) J28.B39(GND14) J28.B40(GND15) J28.B43(GND16) J28.B44(GND17) J28.B47(GND18) J28.B49(GND19) J38.5 J38.8 J39.2 J5006.2 J5010.MINUS J5011.7 J5011.8 J5012.2 J5013.4(GND) J5016.4(GND) J5018.2 LED19.C(CATHODE) P1.A1(GND_(FIXED)) P1.A11(GND_(FIXED)) P1.A21(GND_(FIXED)) P1.A31(GND_(FIXED)) P1.A38(GND) P1.A41(GND_(FIXED)) P1.A51(GND_(FIXED)) P1.A57(GND) P1.A60(GND_(FIXED)) P1.A66(GND) P1.A70(GND_(FIXED)) P1.A73(GND) P1.A76(GND) P1.A79(GND) P1.A80(GND_(FIXED)) P1.A83(GND) P1.A90(GND_(FIXED)) P1.A100(GND_(FIXED)) P1.A110(GND_(FIXED)) P1.B1(GND_(FIXED)) P1.B11(GND_(FIXED)) P1.B21(GND_(FIXED)) P1.B31(GND_(FIXED)) P1.B38(GND) P1.B41(GND_(FIXED)) P1.B51(GND_(FIXED)) P1.B60(GND_(FIXED)) P1.B70(GND_(FIXED)) P1.B73(GND) P1.B76(GND) P1.B79(GND) P1.B80(GND_(FIXED)) P1.B83(GND) P1.B90(GND_(FIXED)) P1.B100(GND_(FIXED)) P1.B110(GND_(FIXED)) P2.A1(GND_(FIXED)) P2.A2(GND) P2.A5(GND) P2.A8(GND) P2.A11(GND(FIXED)) P2.A14(GND) P2.A18(GND) P2.A21(GND_(FIXED)) P2.A25(GND) P2.A28(GND) P2.A31(GND_(FIXED)) P2.A41(GND_(FIXED)) P2.A44(GND) P2.A48(GND) P2.A51(GND_(FIXED)) P2.A60(GND_(FIXED)) P2.A70(GND_(FIXED)) P2.A73(GND) P2.A76(GND) P2.A80(GND_(FIXED)) P2.A84(GND) P2.A87(GND) P2.A90(GND_(FIXED)) P2.A93(GND) P2.A96(GND) P2.A100(GND_(FIXED)) P2.A103(GND) P2.A110(GND_(FIXED)) P2.B1(GND_(FIXED)) P2.B2(GND) P2.B5(GND) P2.B8(GND) P2.B11(GND_(FIXED)) P2.B14(GND) P2.B18(GND) P2.B21(GND_(FIXED)) P2.B25(GND) P2.B28(GND) P2.B31(GND_(FIXED)) P2.B41(GND_(FIXED)) P2.B44(GND) P2.B48(GND) P2.B51(GND_(FIXED)) P2.B60(GND_(FIXED)) P2.B67(GND) P2.B70(GND_(FIXED)) P2.B73(GND) P2.B76(GND) P2.B80(GND_(FIXED)) P2.B84(GND) P2.B87(GND) P2.B90(GND_(FIXED)) P2.B93(GND) P2.B96(GND) P2.B100(GND_(FIXED)) P2.B103(GND) P2.B110(GND_(FIXED)) P12.5(GND) Q2.2(S) R3.2 R65.2 R66.2 R67.2 R115.1 R116.1 R199.1 R468.2 R476.2 R478.2 R479.2 R480.2 R481.1 R484.1 R487.1 R488.1 R491.1 R493.1 R495.1 R504.1 R507.1 R511.2 RN14.5 RN14.6 RN14.7 RN14.8 U2.2(GND/PAD) U5.4(GND) U5.7(GND) U5.13(GND) U5.16(GND) U6.6(VSS1) U6.G1 U6.G2 U6.G3 U6.G4 U7.4(VSS) U9.2(GND) U12.3(GND) U12.13(GND) U12.17(GND) U14.1 U15.12(GND) U18.2(GND) U26.33(VSS) U29.1(GND) U29.4(GND) U29.7(GND) U31.1(GND) U31.4(GND) U31.7(GND) U32.1(GND) U32.4(GND) U32.7(GND) U2027.3 U2027.9 U2027.15 U2027.21 U2027.27 U2027.33 U2027.39 U2027.45 U2027.51 U2027.57 U2027.71 U2027.73 U2027.75 U2028.1(GND) U2028.4(GND) U2028.7(GND) U2029.5(GND) U2029.7(EPAD) U3006.3(GND) U10004.11(TEST) U10004.37(VSS(FLAG)) U10005.5(GND) U10005.7(EPAD) U10006.2(GND) U10007.2(GND) U10009.6(GND) U10010.6(GND) U10011.AB1(GND) U10011.AB10(GND) U10011.AB11(GND) U10011.AB14(GND) U10011.AB17(GND) U10011.AB20(GND) U10011.AT1(GND) U10011.AT10(GND) U10011.AT11(GND) U10011.AT14(GND) U10011.AT17(GND) U10011.AT20(GND) U10011.BB1(GND) U10011.BB10(GND) U10011.BB11(GND) U10011.BB14(GND) U10011.BB17(GND) U10011.BB20(GND) U10011.BT1(GND) U10011.BT10(GND) U10011.BT11(GND) U10011.BT14(GND) U10011.BT17(GND) U10011.BT20(GND) U10012.1 U10013.4(VSS) U10013.24(VSS) U10013.25(GND) U10014.2(GND) Y1.2 Y1.4
GNDC: C57.1 C1012.1 CON9.SH1 CON9.SH2 J15.1(GNDC) J5003.SH1(Earth1) J5003.SH2(Earth2) P12.SH1 P12.SH2 U5.SH1 U5.SH2 U5.SH3 U5.SH4 U10011.SH
V3P3A_FLT: C26.1 FB2.2 U26.5(VDDA)
VBAT_CONNECTED: U26.26(PB3)
VCC_QSFP28: C1062.1 C1063.1 FB24.2 J23.30(VCC1)
VCC_RTC: D1.3(CATHODE) P1.A47(VCC_RTC)
VCC_RX: C215.1 C973.1 FB9.2 J23.10(VCCRX)
VCC_TX: C1060.1 C1061.1 FB23.2 J23.29(VCCTX)
10G_INT0: P2.A47(10G_INT0) U10011.AT6(MODE_ABS)
10G_INT1: P2.B47(10G_INT1) U10011.AB6(MODE_ABS)
10G_INT2: P2.A24(10G_INT2) U10011.BT6(MODE_ABS)
10G_INT3: P2.B24(10G_INT3) U10011.BB6(MODE_ABS)
10G_KR_RXN0: J23.18(RX1N) P2.A50(10G_KR_RX0-)
10G_KR_RXN1: J23.21(RX2N) P2.A43(10G_KR_RX1-)
10G_KR_RXN2: J23.15(RX3N) P2.A30(10G_KR_RX2-)
10G_KR_RXN3: J23.24(RX4N) P2.A27(10G_KR_RX3-)
10G_KR_RXP0: J23.17(RX1P) P2.A49(10G_KR_RX0+)
10G_KR_RXP1: J23.22(RX2P) P2.A42(10G_KR_RX1+)
10G_KR_RXP2: J23.14(RX3P) P2.A29(10G_KR_RX2+)
10G_KR_RXP3: J23.25(RX4P) P2.A26(10G_KR_RX3+)
10G_KR_TXN0: J23.37(TX1N) P2.B50(10G_KR_TX0-)
10G_KR_TXN1: J23.2(TX2N) P2.B43(10G_KR_TX1-)
10G_KR_TXN2: J23.34(TX3N) P2.B30(10G_KR_TX2-)
10G_KR_TXN3: J23.5(TX4N) P2.B27(10G_KR_TX3-)
10G_KR_TXP0: J23.36(TX1P) P2.B49(10G_KR_TX0+)
10G_KR_TXP1: J23.3(TX2P) P2.B42(10G_KR_TX1+)
10G_KR_TXP2: J23.33(TX3P) P2.B29(10G_KR_TX2+)
10G_KR_TXP3: J23.6(TX4P) P2.B26(10G_KR_TX3+)
10G_LED_SCL: P2.A37(10G_LED_SCL)
10G_LED_SDA: P2.A36(10G_LED_SDA)
10G_PHY_CAP_01: P2.B35(10G_PHY_CAP_01)
10G_PHY_CAP_23: P2.B34(10G_PHY_CAP_23)
10G_PHY_MDC_SCL0: P2.A46(10G_PHY_MDC_SCL0)
10G_PHY_MDC_SCL1: P2.A45(10G_PHY_MDC_SCL1)
10G_PHY_MDC_SCL2: P2.A16(10G_PHY_MDC_SCL2) R510.1
10G_PHY_MDC_SCL3: P2.A15(10G_PHY_MDC_SCL3)
10G_PHY_MDIO_SDA0: P2.B46(10G_PHY_MDIO_SDA0)
10G_PHY_MDIO_SDA1: P2.B45(10G_PHY_MDIO_SDA1)
10G_PHY_MDIO_SDA2: P2.B16(10G_PHY_MDIO_SDA2)
10G_PHY_MDIO_SDA3: P2.B15(10G_PHY_MDIO_SDA3)
10G_PHY_RST_01: P2.A35(10G_PHY_RST_01)
10G_PHY_RST_23: P2.A34(10G_PHY_RST_23)
10G_SDP0: P2.A40(10G_SDP0)
10G_SDP1: P2.B40(10G_SDP1)
10G_SDP2: P2.A17(10G_SDP2)
10G_SDP3: P2.B17(10G_SDP3)
10G_SFP_SCL0: P2.B39(10G_SFP_SCL0) U10011.AT5(SCL)
10G_SFP_SCL1: P2.B38(10G_SFP_SCL1) U10011.AB5(SCL)
10G_SFP_SCL2: P2.B33(10G_SFP_SCL2) U10011.BT5(SCL)
10G_SFP_SCL3: P2.B32(10G_SFP_SCL3) U10011.BB5(SCL)
10G_SFP_SDA0: P2.A39(10G_SFP_SDA0) U10011.AT4(SDA)
10G_SFP_SDA1: P2.A38(10G_SFP_SDA1) U10011.AB4(SDA)
10G_SFP_SDA2: P2.A33(10G_SFP_SDA2) U10011.BT4(SDA)
10G_SFP_SDA3: P2.A32(10G_SFP_SDA3) U10011.BB4(SDA)
AB_RS0: R488.2 R489.1 U10011.AB7(RS0)
AB_RS1: R490.1 R491.2 U10011.AB9(RS1)
AB_TX_DIS: RN14.3 U10011.AB3(TX_DISABLE)
AB_VCCR: C1015.1 C1019.1 FB17.2 U10011.AB15(VCCR)
AB_VCCT: C1016.1 C1020.1 FB16.2 U10011.AB16(VCCT)
AT_RS0: R492.1 R493.2 U10011.AT7(RS0)
AT_RS1: R494.1 R495.2 U10011.AT9(RS1)
AT_TX_DIS: RN14.1 U10011.AT3(TX_DISABLE)
AT_VCCR: C393.1 C394.1 C1050.1 C1053.1 C1054.1 C1055.1 C1056.1 C1057.1 FB14.2 FB22.2 U10011.AT15(VCCR) U10013.1(VDD) U10013.3(VDD) U10013.5(OE_DIFF0) U10013.6(VDD) U10013.12(VDD) U10013.17(VDD) U10013.18(OE_DIFF1) U10013.21(VDD)
AT_VCCT: C396.1 C397.1 FB15.2 U10011.AT16(VCCT)
ATX_PS_ONn: CON11.16(PS-ON) J39.1 Q2.3(D)
ATX_PWR_OK: CON11.8(PG) R507.2 U3006.1(INB) U3006.2(INA)
BATLOW#: P1.A27(BATLOW#) TP97.1
BB_RS0: R113.1 R115.2 U10011.BB7(RS0)
BB_RS1: R114.1 R116.2 U10011.BB9(RS1)
BB_TX_DIS: RN14.4 U10011.BB3(TX_DISABLE)
BB_VCCR: C1029.1 C1033.1 FB21.2 U10011.BB15(VCCR)
BB_VCCT: C1030.1 C1034.1 FB20.2 U10011.BB16(VCCT)
BIOS_DIS0#: J5018.1 P1.A34(BIOS_DIS0#/ESPI_SAFS) U26.25(PA15)
BIOS_DIS1#: P1.B88(BIOS_DIS1#/ESPI_BBS)
BT_RS0: R484.2 R485.1 U10011.BT7(RS0)
BT_RS1: R486.1 R487.2 U10011.BT9(RS1)
BT_TX_DIS: RN14.2 U10011.BT3(TX_DISABLE)
BT_VCCR: C1022.1 C1026.1 FB19.2 U10011.BT15(VCCR)
BT_VCCT: C1023.1 C1027.1 FB18.2 U10011.BT16(VCCT)
BTN_CSRD: C998.1 C999.1 U15.5(CSRD)
BTN_HOLD: D3.1(ANODE1) D3.2(ANODE2) R475.1 R476.1 U15.4(PSHOLD)
BTN_VREF: C997.2 U15.3(VREF)
CB_RESET#: J23.9(Reset#) J28.A11(~{PERST}) P1.B50(CB_RESET#) R64.1 R468.1 U2027.50
CLK_SLOT1_N: U2027.53 U10013.13(DIFF0#)
CLK_SLOT1_P: U2027.55 U10013.14(DIFF0)
CLK_SLOT2_N: J28.A14(REFCLK-) U10013.15(DIFF1#)
CLK_SLOT2_P: J28.A13(REFCLK+) U10013.16(DIFF1)
CLKREQ#: U2027.52
COM_PWRBTN#: C976.1 P1.B12(PWRBTN#) U15.8(~{PB}out)
CT_PWP3: C224.2 C225.2 C226.2 C1013.2 J5003.P2
EN: Q2.1(G) U15.9(EN)
FAN_PWM: J10.1(PWM) P1.B101(FAN_PWMOUT)
FAN_TACHIN: J10.2(SENSE) P1.B102(FAN_TACHIN) R509.1
GBE0_ACT#: P1.B2(GBE0_ACT#) R334.1
GBE0_CTREF: P1.A14(GBE0_CTREF)
GBE0_DN0: J5003.P10 P1.A12(GBE0_MDI0-)
GBE0_DN1: J5003.P8 P1.A9(GBE0_MDI1-)
GBE0_DN2: J5003.P6 P1.A6(GBE0_MDI2-)
GBE0_DN3: J5003.P4 P1.A2(GBE0_MDI3-)
GBE0_DP0: J5003.P9 P1.A13(GBE0_MDI0+)
GBE0_DP1: J5003.P7 P1.A10(GBE0_MDI1+)
GBE0_DP2: J5003.P5 P1.A7(GBE0_MDI2+)
GBE0_DP3: J5003.P3 P1.A3(GBE0_MDI3+)
GBE0_LINK100#: J5003.11 P1.A4(GBE0_LINK100#)
GBE0_LINK1000#: P1.A5(GBE0_LINK1000#) R333.1
GBE0_LINK#: P1.A8(GBE0_LINK#)
GPO2: J23.27(ModPrs#) P1.B57(GPO2) R506.1
HDD_LED+: J38.1 R502.2
HUB_CFGSEL0: R66.1 U10004.24(SCL/SMBCLK/CFG_SEL0)
HUB_CFGSEL1: R65.1 U10004.25(HS_IND/CFG_SEL1)
HUB_CRFILT: C114.1 U10004.14(CRFILT)
HUB_NONREM0: R61.2 U10004.28(SUSP_IND/LOCAL_PWR/NON_REM0)
HUB_NONREM1: R479.1 U10004.22(SDA/SMBDATA/NON_REM1)
HUB_PLLFILT: C108.1 U10004.34(PLLFILT)
HUB_RBIAS: R67.1 U10004.35(RBIAS)
HUB_RESET#: C104.1 R63.2 R64.2 U10004.26(~{RESET})
HUB_VBUSDET: R60.2 U10004.27(VBUS_DET)
HUB_XTAL1: C112.1 R68.1 U10004.33(XTAL1/CLKIN) Y1.1
HUB_XTAL2: C113.1 R68.2 U10004.32(XTAL2/CLKIN_EN) Y1.3
I2C_SCL: J23.11(SCL) J28.B5(SMCLK) P1.B33(I2C_CK) R500.2
I2C_SDA: J23.12(SDA) J28.B6(SMDAT) P1.B34(I2C_DAT) R501.2
INT#: U15.11(~{INT})
LID#: P1.A103(LID#) TP115.1
MASTER_RESET#: R503.1 U26.27(PB4)
MCU_ADC_IN8: R37.1 R504.2 U26.14(PB0)
MCU_ADC_IN9: U26.15(PB1)
MCU_I2C1_SCK: R200.2 R499.2 RN15.2 U26.29(PB6)
MCU_I2C1_SDA: R78.2 R498.2 RN15.1 U26.30(PB7)
MCU_RESET: R198.1 U26.4(NRST)
MCU_SPI1_CS: U26.10(PA4) U10009.2(NO1)
MCU_SPI1_MISO: U26.12(PA6) U10010.2(NO1)
MCU_SPI1_MOSI: U26.13(PA7) U10010.10(NO2)
MCU_SPI1_SCK: U26.11(PA5) U10009.10(NO2)
MCU_SPI1_SWITCH: R481.2 U26.16(PB2) U10009.4(SEL1) U10009.8(SEL2) U10010.4(SEL1) U10010.8(SEL2)
MCU_USART1_RX: J5006.1 P1.A98(SER0_TX) U12.2(RXD) U26.20(PA10)
MCU_USART1_TX: R497.1 U26.19(PA9)
MCU_USART2_RX: TP124.1 U26.9(PA3)
MCU_USART2_TX: TP125.1 U26.8(PA2)
NCSI_ARB_IN: P1.B98(NCSI_ARB_IN) TP113.1
NCSI_ARB_OUT: P1.B99(NCSI_ARB_OUT) TP114.1
NCSI_CLK_IN: P1.B91(NCSI_CLK_IN) TP107.1
NCSI_CRS_DV: P1.B94(NCSI_CRS_DV) TP110.1
NCSI_RXD0: P1.B93(NCSI_RXD0) TP109.1
NCSI_RXD1: P1.B92(NCSI_RXD1) TP108.1
NCSI_TRI_EN: P1.B89(NCSI_TRI_EN) TP106.1
NCSI_TX_EN: P1.A84(NCSI_TX_EN) TP105.1
NCSI_TXD0: P1.B96(NCSI_TXD0) TP112.1
NCSI_TXD1: P1.B95(NCSI_TXD1) TP111.1
NVME_LED#: J38.3 U2027.10 U10014.1(IO1)
OC#1: U10004.13(~{OCS1})
OC#2: U10004.17(~{OCS2})
OC#3: U10004.19(~{OCS3})
OC#4: U10004.21(~{OCS4})
PCIE_CKREF_N: P1.A89(PCIE_CK_REF-) U10013.23(DIFF_IN#)
PCIE_CKREF_P: P1.A88(PCIE_CK_REF+) U10013.22(DIFF_IN)
PCIE_RXN0: P1.B69(PCIE_RX0-) U2027.41
PCIE_RXN1: P1.B65(PCIE_RX1-) U2027.29
PCIE_RXN2: P1.B62(PCIE_RX2-) U2027.17
PCIE_RXN3: P1.B59(PCIE_RX3-) U2027.5
PCIE_RXN4: C330.1 P1.B56(PCIE_RX4-)
PCIE_RXN5: C985.1 P1.B53(PCIE_RX5-)
PCIE_RXN6: P2.A20(PCIE_RX6-)
PCIE_RXN7: P2.A23(PCIE_RX7-)
PCIE_RXN8: J28.A17(PERN0) P1.B72(PCIE_RX8-)
PCIE_RXN9: J28.A22(PERN1) P1.B75(PCIE_RX9-)
PCIE_RXN10: J28.A26(PERN2) P1.B78(PCIE_RX10-)
PCIE_RXN11: J28.A30(PERN3) P1.B82(PCIE_RX11-)
PCIE_RXN12: J28.A36(PERN4) P1.B40(PCIE_RX12-)
PCIE_RXN13: J28.A40(PERN5) P1.B37(PCIE_RX13-)
PCIE_RXN14: J28.A44(PERN6) P1.B26(PCIE_RX14-)
PCIE_RXN15: J28.A48(PERN7) P1.B23(PCIE_RX15-)
PCIE_RXN16: P2.A53(PCIE_RX16-) U10011.AT12(RX-)
PCIE_RXN17: P2.A56(PCIE_RX17-) U10011.AB12(RX-)
PCIE_RXN18: P2.A59(PCIE_RX18-) U10011.BT12(RX-)
PCIE_RXN19: P2.A62(PCIE_RX19-) U10011.BB12(RX-)
PCIE_RXN20: P2.A66(PCIE_RX20-)
PCIE_RXN21: P2.A69(PCIE_RX21-)
PCIE_RXN22: P2.A72(PCIE_RX22-)
PCIE_RXN23: P2.A75(PCIE_RX23-)
PCIE_RXN24: P2.A79(PCIE_RX24-)
PCIE_RXN25: P2.A82(PCIE_RX25-)
PCIE_RXN26: P2.A86(PCIE_RX26-)
PCIE_RXN27: P2.A89(PCIE_RX27-)
PCIE_RXN28: P2.A92(PCIE_RX28-)
PCIE_RXN29: P2.A95(PCIE_RX29-)
PCIE_RXN30: P2.A99(PCIE_RX30-)
PCIE_RXN31: P2.A102(PCIE_RX31-)
PCIE_RXP0: P1.B68(PCIE_RX0+) U2027.43
PCIE_RXP1: P1.B64(PCIE_RX1+) U2027.31
PCIE_RXP2: P1.B61(PCIE_RX2+) U2027.19
PCIE_RXP3: P1.B58(PCIE_RX3+) U2027.7
PCIE_RXP4: C331.1 P1.B55(PCIE_RX4+)
PCIE_RXP5: C986.1 P1.B52(PCIE_RX5+)
PCIE_RXP6: P2.A19(PCIE_RX6+)
PCIE_RXP7: P2.A22(PCIE_RX7+)
PCIE_RXP8: J28.A16(PERP0) P1.B71(PCIE_RX8+)
PCIE_RXP9: J28.A21(PERP1) P1.B74(PCIE_RX9+)
PCIE_RXP10: J28.A25(PERP2) P1.B77(PCIE_RX10+)
PCIE_RXP11: J28.A29(PERP3) P1.B81(PCIE_RX11+)
PCIE_RXP12: J28.A35(PERP4) P1.B39(PCIE_RX12+)
PCIE_RXP13: J28.A39(PERP5) P1.B36(PCIE_RX13+)
PCIE_RXP14: J28.A43(PERP6) P1.B25(PCIE_RX14+)
PCIE_RXP15: J28.A47(PERP7) P1.B22(PCIE_RX15+)
PCIE_RXP16: P2.A52(PCIE_RX16+) U10011.AT13(RX+)
PCIE_RXP17: P2.A55(PCIE_RX17+) U10011.AB13(RX+)
PCIE_RXP18: P2.A58(PCIE_RX18+) U10011.BT13(RX+)
PCIE_RXP19: P2.A61(PCIE_RX19+) U10011.BB13(RX+)
PCIE_RXP20: P2.A65(PCIE_RX20+)
PCIE_RXP21: P2.A68(PCIE_RX21+)
PCIE_RXP22: P2.A71(PCIE_RX22+)
PCIE_RXP23: P2.A74(PCIE_RX23+)
PCIE_RXP24: P2.A78(PCIE_RX24+)
PCIE_RXP25: P2.A81(PCIE_RX25+)
PCIE_RXP26: P2.A85(PCIE_RX26+)
PCIE_RXP27: P2.A88(PCIE_RX27+)
PCIE_RXP28: P2.A91(PCIE_RX28+)
PCIE_RXP29: P2.A94(PCIE_RX29+)
PCIE_RXP30: P2.A98(PCIE_RX30+)
PCIE_RXP31: P2.A101(PCIE_RX31+)
PCIE_TXN0: P1.A69(PCIE_TX0-) U2027.47
PCIE_TXN1: P1.A65(PCIE_TX1-) U2027.35
PCIE_TXN2: P1.A62(PCIE_TX2-) U2027.23
PCIE_TXN3: P1.A59(PCIE_TX3-) U2027.11
PCIE_TXN4: P1.A56(PCIE_TX4-) U32.3(TXn)
PCIE_TXN5: P1.A53(PCIE_TX5-) U2028.3(TXn)
PCIE_TXN6: P2.B20(PCIE_TX6-)
PCIE_TXN7: P2.B23(PCIE_TX7-)
PCIE_TXN8: J28.B15(PETN0) P1.A72(PCIE_TX8-)
PCIE_TXN9: J28.B20(PETN1) P1.A75(PCIE_TX9-)
PCIE_TXN10: J28.B24(PETN2) P1.A78(PCIE_TX10-)
PCIE_TXN11: J28.B28(PETN3) P1.A82(PCIE_TX11-)
PCIE_TXN12: J28.B34(PETN4) P1.A40(PCIE_TX12-)
PCIE_TXN13: J28.B38(PETN5) P1.A37(PCIE_TX13-)
PCIE_TXN14: J28.B42(PETN6) P1.A26(PCIE_TX14-)
PCIE_TXN15: J28.B46(PETN7) P1.A23(PCIE_TX15-)
PCIE_TXN16: P2.B53(PCIE_TX16-) U10011.AT19(TX-)
PCIE_TXN17: P2.B56(PCIE_TX17-) U10011.AB19(TX-)
PCIE_TXN18: P2.B59(PCIE_TX18-) U10011.BT19(TX-)
PCIE_TXN19: P2.B62(PCIE_TX19-) U10011.BB19(TX-)
PCIE_TXN20: P2.B66(PCIE_TX20-)
PCIE_TXN21: P2.B69(PCIE_TX21-)
PCIE_TXN22: P2.B72(PCIE_TX22-)
PCIE_TXN23: P2.B75(PCIE_TX23-)
PCIE_TXN24: P2.B79(PCIE_TX24-)
PCIE_TXN25: P2.B82(PCIE_TX25-)
PCIE_TXN26: P2.B86(PCIE_TX26-)
PCIE_TXN27: P2.B89(PCIE_TX27-)
PCIE_TXN28: P2.B92(PCIE_TX28-)
PCIE_TXN29: P2.B95(PCIE_TX29-)
PCIE_TXN30: P2.B99(PCIE_TX30-)
PCIE_TXN31: P2.B102(PCIE_TX31-)
PCIE_TXP0: P1.A68(PCIE_TX0+) U2027.49
PCIE_TXP1: P1.A64(PCIE_TX1+) U2027.37
PCIE_TXP2: P1.A61(PCIE_TX2+) U2027.25
PCIE_TXP3: P1.A58(PCIE_TX3+) U2027.13
PCIE_TXP4: P1.A55(PCIE_TX4+) U32.2(TXp)
PCIE_TXP5: P1.A52(PCIE_TX5+) U2028.2(TXp)
PCIE_TXP6: P2.B19(PCIE_TX6+)
PCIE_TXP7: P2.B22(PCIE_TX7+)
PCIE_TXP8: J28.B14(PETP0) P1.A71(PCIE_TX8+)
PCIE_TXP9: J28.B19(PETP1) P1.A74(PCIE_TX9+)
PCIE_TXP10: J28.B23(PETP2) P1.A77(PCIE_TX10+)
PCIE_TXP11: J28.B27(PETP3) P1.A81(PCIE_TX11+)
PCIE_TXP12: J28.B33(PETP4) P1.A39(PCIE_TX12+)
PCIE_TXP13: J28.B37(PETP5) P1.A36(PCIE_TX13+)
PCIE_TXP14: J28.B41(PETP6) P1.A25(PCIE_TX14+)
PCIE_TXP15: J28.B45(PETP7) P1.A22(PCIE_TX15+)
PCIE_TXP16: P2.B52(PCIE_TX16+) U10011.AT18(TX+)
PCIE_TXP17: P2.B55(PCIE_TX17+) U10011.AB18(TX+)
PCIE_TXP18: P2.B58(PCIE_TX18+) U10011.BT18(TX+)
PCIE_TXP19: P2.B61(PCIE_TX19+) U10011.BB18(TX+)
PCIE_TXP20: P2.B65(PCIE_TX20+)
PCIE_TXP21: P2.B68(PCIE_TX21+)
PCIE_TXP22: P2.B71(PCIE_TX22+)
PCIE_TXP23: P2.B74(PCIE_TX23+)
PCIE_TXP24: P2.B78(PCIE_TX24+)
PCIE_TXP25: P2.B81(PCIE_TX25+)
PCIE_TXP26: P2.B85(PCIE_TX26+)
PCIE_TXP27: P2.B88(PCIE_TX27+)
PCIE_TXP28: P2.B91(PCIE_TX28+)
PCIE_TXP29: P2.B94(PCIE_TX29+)
PCIE_TXP30: P2.B98(PCIE_TX30+)
PCIE_TXP31: P2.B101(PCIE_TX31+)
PCIE_WAKE#: P1.B66(WAKE0#)
PEWAKE#: U2027.54
PLA#: U2027.30
PLN#: U2027.8
PRSNT_SLOT2_B: J28.B17(~{PRSNT2}_1) J28.B31(~{PRSNT2}_2) J28.B48(~{PRSNT2}_3)
PWM: J5013.1(PWM) J5016.1(PWM)
PWON1: U10004.12(PRTPWR1)
PWON2: U10004.16(PRTPWR2)
PWON3: U10004.18(PRTPWR3)
PWON4: U10004.20(PRTPWR4)
PWR_BTN: D15.3(CATHODE) U26.28(PB5)
PWR_LED-: J38.4
PWR_OK: P1.B24(PWR_OK) U3006.4(OUT)
PWRBTN_CNTRLR#: C1.1 C2.1 D8.1(ANODE1) D8.2(ANODE2) D14.1(ANODE1) D14.2(ANODE2) D15.1(ANODE1) D15.2(ANODE2) U15.2(~{SR}) U15.6(~{PB}) U10012.2
PWRBTN_PANEL#: D14.3(CATHODE) J38.6 U10014.4(IO3)
RST#: U15.10(~{RST})
SATA0_RXN: P1.A20(SATA0_RX-) U29.5(RXn)
SATA0_RXP: P1.A19(SATA0_RX+) U29.6(RXp)
SATA0_TXN: P1.A17(SATA0_TX-) U29.3(TXn)
SATA0_TXP: P1.A16(SATA0_TX+) U29.2(TXp)
SATA1_RXN: P1.B20(SATA1_RX-) U31.5(RXn)
SATA1_RXP: P1.B19(SATA1_RX+) U31.6(RXp)
SATA1_TXN: P1.B17(SATA1_TX-) U31.3(TXn)
SATA1_TXP: P1.B16(SATA1_TX+) U31.2(TXp)
SATA_ACT#: P1.A28(SATA_ACT#)
SD_CD: P1.B63(GPO3/SD_CD) U6.9(Cd)
SD_CLK: P1.A93(GPO0) U6.5(CLK)
SD_CMD: P1.B54(GPO1) U6.3(CMD)
SD_D0: P1.A54(GPI0) U6.7(D0)
SD_D1: P1.A63(GPI1) U6.8(D1)
SD_D2: P1.A67(GPI2) U6.1(D2)
SD_D3: P1.A85(GPI3) U6.2(CD/D3)
SEC_SPI_3v0: C58.1 D12.3(CATHODE) R22.2 R23.2 R508.2 U7.8(VCC) U10009.1(VCC) U10010.1(VCC)
SEC_SPI_CLK: C103.2 U7.6(C) U10009.9(COM2)
SEC_SPI_CS#: R508.1 U7.1(~{S}) U10009.3(COM1)
SEC_SPI_MISO: U7.2(Q) U10010.3(COM1)
SEC_SPI_MOSI: U7.5(D) U10010.9(COM2)
SENSE: J5013.2(SENSE) J5016.2(SENSE)
SER0_RX: J5006.3 P1.A99(SER0_RX) R496.2 R497.2
SER1_RX: J5012.3 P1.A102(CAN0/SER1_RX)
SER1_TX: J5012.1 P1.A101(CAN0/SER1_TX)
SLEEP#: P1.B103(SLEEP#) TP116.1
SLOT2_WAKE_B: J28.B11(~{WAKE}) TP117.1(TP)
SLP_S3#: P1.A15(SUS_S3#)
SLP_S4#: P1.A18(SUS_S4#)
SMB_ALRT#: P1.B15(SMB_ALERT#) TP98.1
SMB_CLK: P1.B13(SMB_CK) R498.1
SMB_SDA: P1.B14(SMB_DAT) R499.1
SPI_CLK: P1.A94(SPI_CLK) U10009.7(NC2)
SPI_CS#: P1.B97(SPI_CS#) U10009.5(NC1)
SPI_MISO: P1.A92(SPI_MISO) U10010.5(NC1)
SPI_MOSI: P1.A95(SPI_MOSI) U10010.7(NC2)
SPI_NOR_HOLD_B: R22.1 U7.7(~{HOLD})
SPI_NOR_WP: R23.1 U7.3(~{W}/VPP)
SPI_POWER: D12.1(ANODE1) P1.A91(SPI_POWER)
SPKR: P1.B32(SPKR) TP101.1
SUS_S5#: D3.3(CATHODE) P1.A24(SUS_S5#) TP99.1
SYS_RESET#: C94.1 J38.7 P1.B49(SYS_RESET#) R503.2 U14.2 U10014.3(IO2)
THRM: P1.B35(THRM#) TP103.1
THRMTRIP#: P1.A35(THRMTRIP#) TP102.1
TYPE0#: P2.A54(TYPE0#)
TYPE1#: P2.A57(TYPE1#)
TYPE2#: P2.B57(TYPE2#)
USB0_DN: P1.A45(USB0-) U5.2(D1-) U10007.1(IO1)
USB0_DP: P1.A46(USB0+) U5.3(D1+) U10007.3(IO2)
USB1_DN: CON5.8(P1_D-) P1.B45(USB1-) U18.3(IO2)
USB1_DP: CON5.9(P1_D+) P1.B46(USB1+) U18.1(IO1)
USB2_DN: P1.A42(USB2-) U5.11(D2-) U10007.6(IO4)
USB2_DP: P1.A43(USB2+) U5.12(D2+) U10007.4(IO3)
USB3_DN: P1.B42(USB3-) U10004.30(USBUP_DM)
USB3_DP: P1.B43(USB3+) U10004.31(USBUP_DP)
USB_DM: C994.1 P12.2(D-) R473.1
USB_DP: C995.1 P12.3(D+) R474.1
USB_FT_DM: R473.2 U26.21(PA11)
USB_FT_DP: R474.2 U26.22(PA12)
USB_N1: U10004.1(USBDN1_DM)
USB_N2: CON5.12(P2_D-) U18.4(IO3) U10004.3(USBDN2_DM)
USB_N3: J5011.3 U10004.6(USBDN3_DM) U10006.3(IO2)
USB_N4: J5011.4 U10004.8(USBDN4_DM) U10006.4(IO3)
USB_P1: U10004.2(USBDN1_DP)
USB_P2: CON5.11(P2_D+) U18.6(IO4) U10004.4(USBDN2_DP)
USB_P3: J5011.5 U10004.7(USBDN3_DP) U10006.1(IO1)
USB_P4: J5011.6 U10004.9(USBDN4_DP) U10006.6(IO4)
USB_SSRX_N0: D10.2(I/O2) D10.9(NC) P2.A3(USB_SSRX0-) U5.5(SSRX1-)
USB_SSRX_N1: CON5.2(P1_RX-) D11.1(I/O1) D11.10(NC) P2.A6(USB_SSRX1-)
USB_SSRX_N2: D10.4(I/O3) D10.7(NC) P2.A9(USB_SSRX2-) U5.15(SSRX2+)
USB_SSRX_N3: P2.A12(USB_SSRX3-)
USB_SSRX_P0: D10.1(I/O1) D10.10(NC) P2.A4(USB_SSRX0+) U5.6(SSRX1+)
USB_SSRX_P1: CON5.3(P1_RX+) D11.2(I/O2) D11.9(NC) P2.A7(USB_SSRX1+)
USB_SSRX_P2: D10.5(I/O4) D10.6(NC) P2.A10(USB_SSRX2+) U5.14(SSRX2-)
USB_SSRX_P3: P2.A13(USB_SSRX3+)
USB_SSTX_N0: D13.1(I/O1) D13.10(NC) P2.B3(USB_SSTX0-) U5.8(SSTX1-)
USB_SSTX_N1: CON5.5(P1_TX-) D11.4(I/O3) D11.7(NC) P2.B6(USB_SSTX1-)
USB_SSTX_N2: D13.5(I/O4) D13.6(NC) P2.B9(USB_SSTX2-) U5.18(SSTX2+)
USB_SSTX_N3: P2.B12(USB_SSTX3-)
USB_SSTX_P0: D13.2(I/O2) D13.9(NC) P2.B4(USB_SSTX0+) U5.9(SSTX1+)
USB_SSTX_P1: CON5.6(P1_TX+) D11.5(I/O4) D11.6(NC) P2.B7(USB_SSTX1+)
USB_SSTX_P2: D13.4(I/O3) D13.7(NC) P2.B10(USB_SSTX2+) U5.17(SSTX2-)
USB_SSTX_P3: P2.B13(USB_SSTX3+)
V_3.3: C46.1 C55.1 C56.1 C105.1 C106.1 C107.1 C109.1 C110.1 C111.1 C115.1 C174.2 C175.2 C176.2 C216.1 C227.1 C391.1 C392.1 C395.1 C987.1 C1017.1 C1018.1 C1021.1 C1024.1 C1025.1 C1028.1 C1031.1 C1032.1 C1035.1 C1041.2 C1051.1 C1052.1 C1058.2 C1059.1 CON11.1(+3.3V[0]) CON11.2(+3.3V[1]) CON11.12(+3.3V[2]) CON11.13(+3.3V[3]) D1.1(ANODE1) FB9.1 FB14.1 FB15.1 FB16.1 FB17.1 FB18.1 FB19.1 FB20.1 FB21.1 FB22.1 FB23.1 FB24.1 J28.A9(+3.3V_1) J28.A10(+3.3V_2) J28.B8(+3.3V) J28.B10(3.3VAUX) J5003.13 R60.1 R61.1 R63.1 R113.2 R114.2 R467.1 R475.2 R485.2 R486.2 R489.2 R490.2 R492.2 R494.2 R502.1 R506.2 R509.2 U6.4(VDD) U2027.2 U2027.4 U2027.12 U2027.14 U2027.16 U2027.18 U2027.70 U2027.72 U2027.74 U3006.5(VCC) U10004.5(VDDA33) U10004.10(VDDA33) U10004.15(VDD33(REG)) U10004.23(VDD33(IO)) U10004.29(VDDA33) U10004.36(VDDPLLREF/VDDA33)
V_5: C1001.2 C1006.2 C1042.2 C1043.2 C1044.2 C1045.2 CON11.4(+5V[0]) CON11.6(+5V[1]) CON11.21(+5V[2]) CON11.22(+5V[3]) CON11.23(+5V[4]) U2029.4(EN) U2029.6(IN) U10005.4(EN) U10005.6(IN)
V_5_SB: C3.1 C1046.2 C1047.2 CON11.9(+5VSB) P1.B84(VCC_5V_SBY) P1.B85(VCC_5V_SBY) P1.B86(VCC_5V_SBY) P1.B87(VCC_5V_SBY) U2.1(VIN)
V_5V0_4P_USB_2_0: C1005.1 C1007.2 C1008.2 C1009.1 J5011.1 J5011.2 U5.1(VBUS1) U5.10(VBUS2) U10005.1(OUT) U10006.5(VBUS) U10007.5(VBUS)
V_5V0_USB3_HDR_VBUS: C1000.1 C1002.2 C1003.2 C1004.1 CON5.1(VBUS) CON5.19(VBUS) J38.2 J38.9 U18.5(VBUS) U2029.1(OUT) U10014.5(VBUS)
V_MGT_3p3: C236.1 C429.1 C989.1 D12.2(ANODE2) FB2.1 J5017.1 R78.1 R197.2 R198.2 R200.1 RN15.5 RN15.6 RN15.7 RN15.8 U9.4(VOUT) U26.1(VDD) U26.17(VDDIO2)
V_MGT_5p0: C988.2 C993.1 L16.2 U9.1(EN) U9.3(VIN)
WAKE1#: P1.B67(WAKE1#) TP104.1
WDT: P1.B27(WDT) TP100.1
N17088991: C93.2 C972.1 U12.1(VCCIO) U12.8(3V3OUT) U12.9(RESET#)
N17089017: C87.1 C88.2 FB1.1 U12.10(VCC)
N17089025: CON9.1(VBUS) FB1.2
N17089039: CON9.3(D+) U12.6(USBDP)
N17089060: CON9.2(D-) U12.7(USBDM)
N18534349: LED19.A(ANODE) R467.2
N18649190: C330.2 U32.5(RXn)
N18649196: C331.2 U32.6(RXp)
N18679523: C985.2 U2028.5(RXn)
N18679529: C986.2 U2028.6(RXp)
N18690247: C4.1 C996.1 D8.3(CATHODE) R3.1 U2.3(VOUT) U15.1(VCC)
N18691020: D1.2(ANODE2) R41.2
N18691058: J5010.PLUS R41.1
N18691864: C237.1 U9.6(BYP)
N18691932: C992.1 L16.1 P12.1(VBUS)
N18693405: J5017.2 R197.1 R199.2 U26.31(BOOT0-PF11)
N18710663: R478.1 U2029.2(ILIM)
N18738489: J5003.12 R333.2
N18738529: J5003.14 R334.2
N18769152: R496.1 U12.15(TXD)
N18799422: R500.1 U10013.19(SCK)
N18799425: R501.1 U10013.20(SDA)
N18807427: J23.8(ModSeI#) TP121.1(TP)
N18807494: J23.28(Int#) TP122.1(TP)
N18807499: J23.31(LPMode) TP123.1(TP)
N18863454: R480.1 U10005.2(ILIM)
N18893006: C1064.1 R510.2
N18897049: R511.1 U2027.38

Not connected (* = marked no-connect by the designer): CON5 10(ID) 14(P2_TX+) 15(P2_TX-) 17(P2_RX+) 18(P2_RX-); CON9 4(ID)*; CON11 14(-12V) 20(-5V); J28 A5(JTAG_TCK)* A6(JTAG_TDI)* A7(JTAG_TDO)* A8(JTAG_TMS)* A19(RSVD3)* A32(RSVD4)* A33(RSVD5)* B9(JTAG_~{TRST})* B12(RSVD1)* B30(RSVD2)*; J34 1; J41 1; J42 1; J43 1; J44 1; J45 1; J5003 P1; J5007 1; J5008 1; J5011 9*; P1 A29(RSVD)* A30(RSVD)* A32(RSVD)* A33(RSVD)* A44(USB_2_3_OC#)* A48(RSVD)* A49(RSVD)* A50(LPC_SERIRQ/ESPI_CS1#)* A86(RSVD)* A87(RSVD)* A96(TPM_PP) A97(TYPE10#)* B3(LPC_FRAME#/ESPI_CS0#)* B4(LPC_AD0/ESPI_IO_0)* B5(LPC_AD0/ESPI_IO_1)* B6(LPC_AD0/ESPI_IO_2)* B7(LPC_AD0/ESPI_IO_3)* B8(LPC_DRQ0#/ESPI_ALERT0#)* B9(LPC_DRQ1#/ESPI_ALERT1#)* B10(LPC_CLK/ESPI_CK)* B18(SUS_STAT#/ESPI_RESET#)* B28(RSVD)* B29(RSVD)* B30(RSVD)* B44(USB_0_1_OC#)* B47(ESPI_EN)* B48(RSVD)*; P2 A63(RSVD) A64(RSVD) A67(RAPID_SHUTDOWN_(RSVD)) A77(RSVD) A83(RSVD) A97(RSVD) B36(RSVD) B37(RSVD) B54(RSVD) B63(RSVD) B64(RSVD) B77(RSVD) B83(RSVD) B97(RSVD); P12 4(ID)*; RN15 3 4; U9 5(NC)*; U12 4(CTS#)* 5(CBUS2)* 11(CBUS1)* 12(CBUS0)* 14(CBUS3)* 16(RTS#)*; U15 7(~{VCC}lo)*; U26 2(PF0-OSC_IN) 3(PF1-OSC_OUT) 6(PA0) 7(PA1) 18(PA8) 23(PA13) 24(PA14) 32(PB8); U2027 1 6* 20* 22* 24* 26* 28* 32* 34* 36* 40* 42* 44* 46* 48* 56* 58* 59* 60* 61* 62* 63* 64* 65* 66* 67 68 69; U2029 3(FLAG#); U10005 3(FLAG#); U10011 AB2(TX_FAULT) AB8(LOS) AT2(TX_FAULT)* AT8(LOS)* BB2(TX_FAULT) BB8(LOS) BT2(TX_FAULT) BT8(LOS); U10014 6(IO4)*

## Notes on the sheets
sheet 1
- COM express type 7 AB connector
- COM express type 7 AB connector
- The below RC circuit is single ended filter for the
  MDC clock coming from the COM module.
  This is a must since the same MDC is used to control
  the 1Gbps PHY on the COM module and this filter
  avoids reflections from the unconnected stub.
- SD Card 1.8v/3.3v support -
  GPI0 - SD D0
  GPI1 - SD D1
  GPI2 - SD D2
  GPI3 - SD D3
  GPO0 - SD CLK
  GPO1 - SD CMD
  GPO3 - SD CD#
- Bottom left
- Bottom middle
- Bottom right
- Upper left
- Bottom right
sheet 2
- 3 x SATA gen 3.0 connectors
- Note on U32 and U2028 connectors -
  TX AC-caps are on module since those are SERDES lines that are defined
  as PCIe in COM-express and repurposed as SATA via SD2 protocol config #5.
  Due to that RX AC-caps must be on carrier board
- 4 ports USB 2.0 hub
- micro SD connector (bootable)
- OCS ARE INTERNAL PULL-UP, 5.5V TOLERANT
- Note on U29 and U31 connectors
  Per the COM express type 7 spec; the native COM express type 7 SATA ports TX/RX AC-caps are on module.
- POWER ON OUTPUTS ARE ACTIVE HIGH
- NON-REM[1:0]
  '00' - ALL REMOVABLE
  '01' - PORT 1 IS NON-REMOVABLE
  '10' - PORTS 1 AND 2 ARE NON-REMOVABLE
  '11' - PORTS 1, 2 AND 3 ARE NON-REMOVABLE
  IN THIS DESIGN NON-REM[1:0] ARE SET TO
  '01' - PORT 1 IS NON-REMOVABLE
- 3 x Standard 4 pin FAN headers
  with one supporting PWM and TACH.
- Notes -
  1. The FAN connector can accomodate 2 and 3 pin header fans since the plastic part can accomodate that.
  2. LX2K-COM express type 7 rev 1.3 does not support PWM and TACH; only on rev 1.4 and onwords
- TACH pull-up is a workaround for LX2160 COM rev 1.3
- GBE0_CTREF can be left floating
- PCI express 8 lanes connector - open slot
- QSFP28 connector
- Bug notice -
  ModSel# signal in rev 1.1 is floating where it must be grounded in order
  for the QSFP module I2C to be selected.
  As a workaround ModSel# is fixed by externally wiring TP121 to GND.
  This bug is fixed in future revisions.
- Split to 3 domains
sheet 3
- USB 2.0/3.0 host and header connector
- M.2 M key (NVME)
- Reset button and header
- Bring LED to the front?
- Notice that the dual USB 3.0 header that is intended to be used
  with standard PC chassis USB 3.0 front panel will support a single USB 3.0
  and the second USB will be only USB 2.0.
- Reset header can be brought to front panel
- RESET button
- SUSCLK
- PEDET
- NVME 2280
- NVME 2242
- NVME 22110
- Management interface.
  I2C goes to a fixed local EEPROM that has board signature.
  SPI goes to local application processor boot flash
  UART goes to local application processor UART console interface
- Micro BMC
- Workaround for LX2160A rev 1.3 bug not having pull-up on CS
- When jumper inserted; MCU DFU boots
- PA8..PA15 are supplied by VDDIO2
- Onboard micro USB to serial console
sheet 4
- Power-on push button controller
- 2x2 SFP+ connector
- 43mA @ 24V
- 18.5mA @ 12V
- 3.3V@0.33mA
- Vih = 1.05V
- OPEN DRAIN
- OPEN DRAIN
- INT. 100K PU
- RESET button
- ATX PSU connector
- Timing constant = 10s/uF
- Only 12v part is used. Notice the pin 16 to GND short
  that enables the PSU.
- Notes -
  1. The push-butoon controller is configured in a way that powers-on when ATX power is available.
  2. COM express type 7 can shutdnwo the ATX PSU via SUS_S5# signal.
  3. STM32 MCU (micro BMC) can shutdown the motherboard using PWRBTN_CNTRLR# signal.
  3. PC workstation front panel can shutdown the motherboard via PWRBTN_PANEL# signal
  4. COM express type #7 can get indication of power-button being pressed by COM_PWRBTN# (and thus start a shutdown process).
- PCIe clock buffer. Input from COM express type 7 and
  output is connected to the NVME M.2 connector and
  PCIe x8 open-slot connector
- By default DNP.
